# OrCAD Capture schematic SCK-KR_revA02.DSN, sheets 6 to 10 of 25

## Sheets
6 SOM240_1 Connector: size Custom
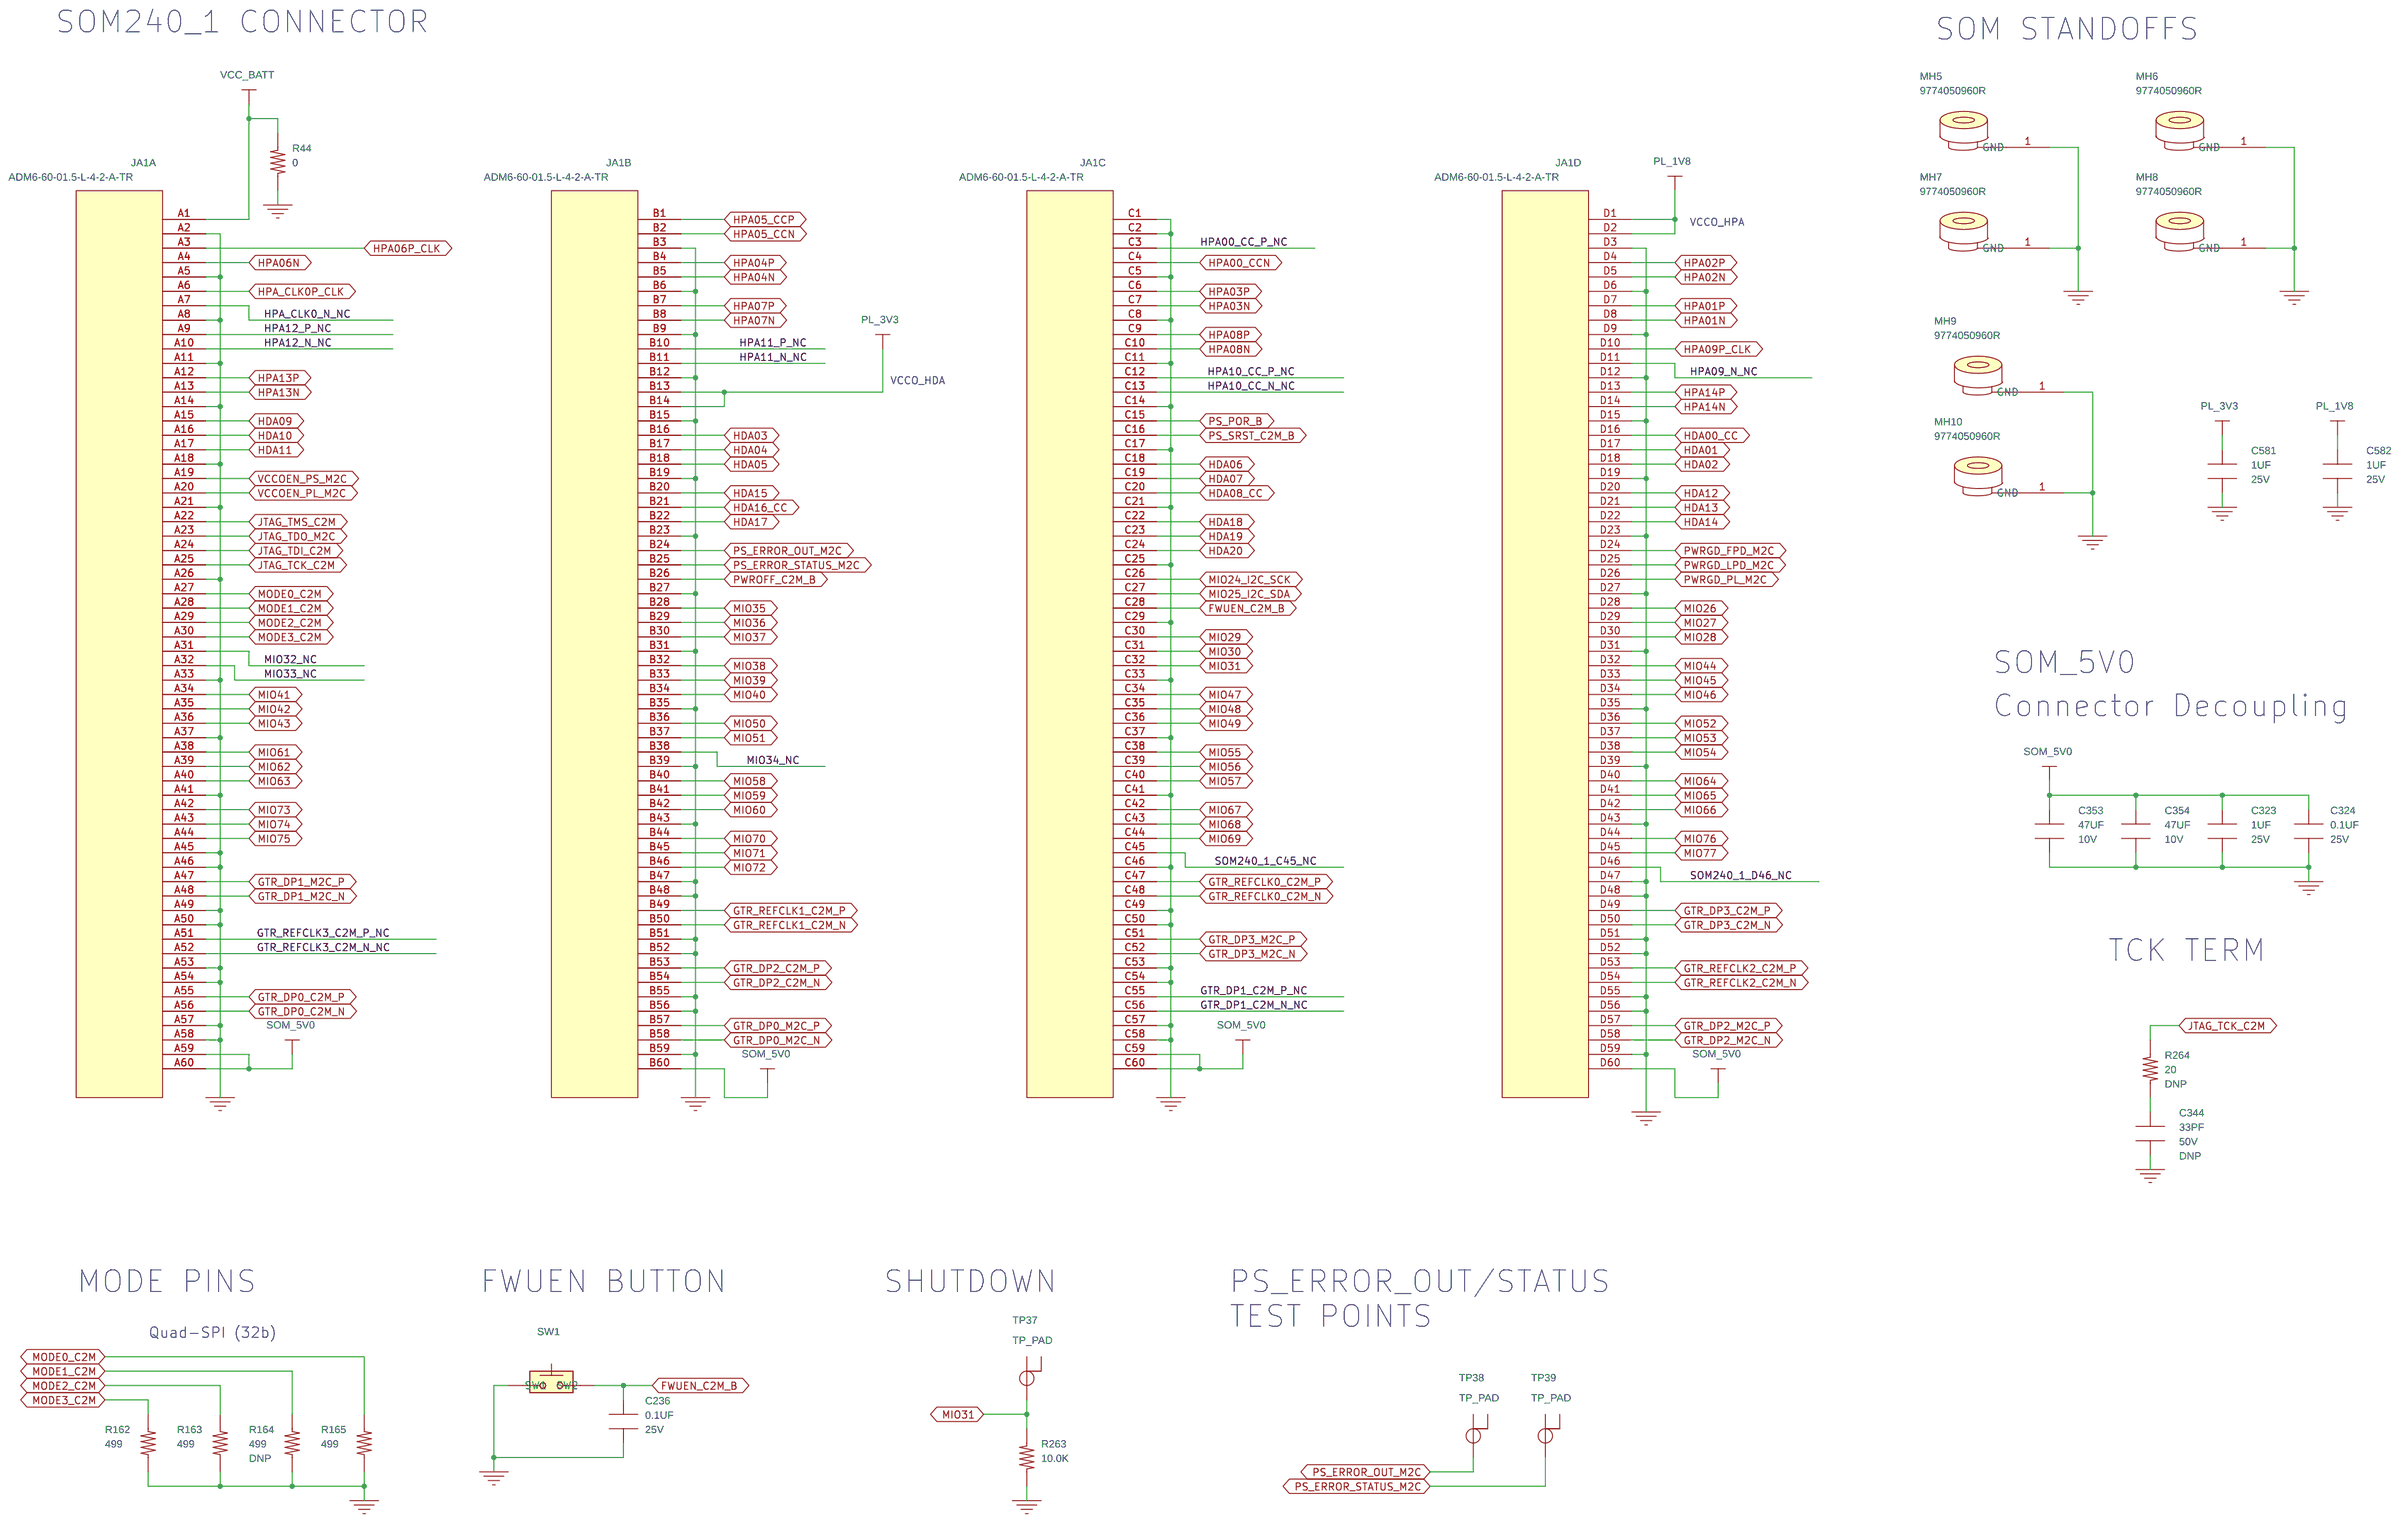
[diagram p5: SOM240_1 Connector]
7 SOM240_2 Connector: size Custom
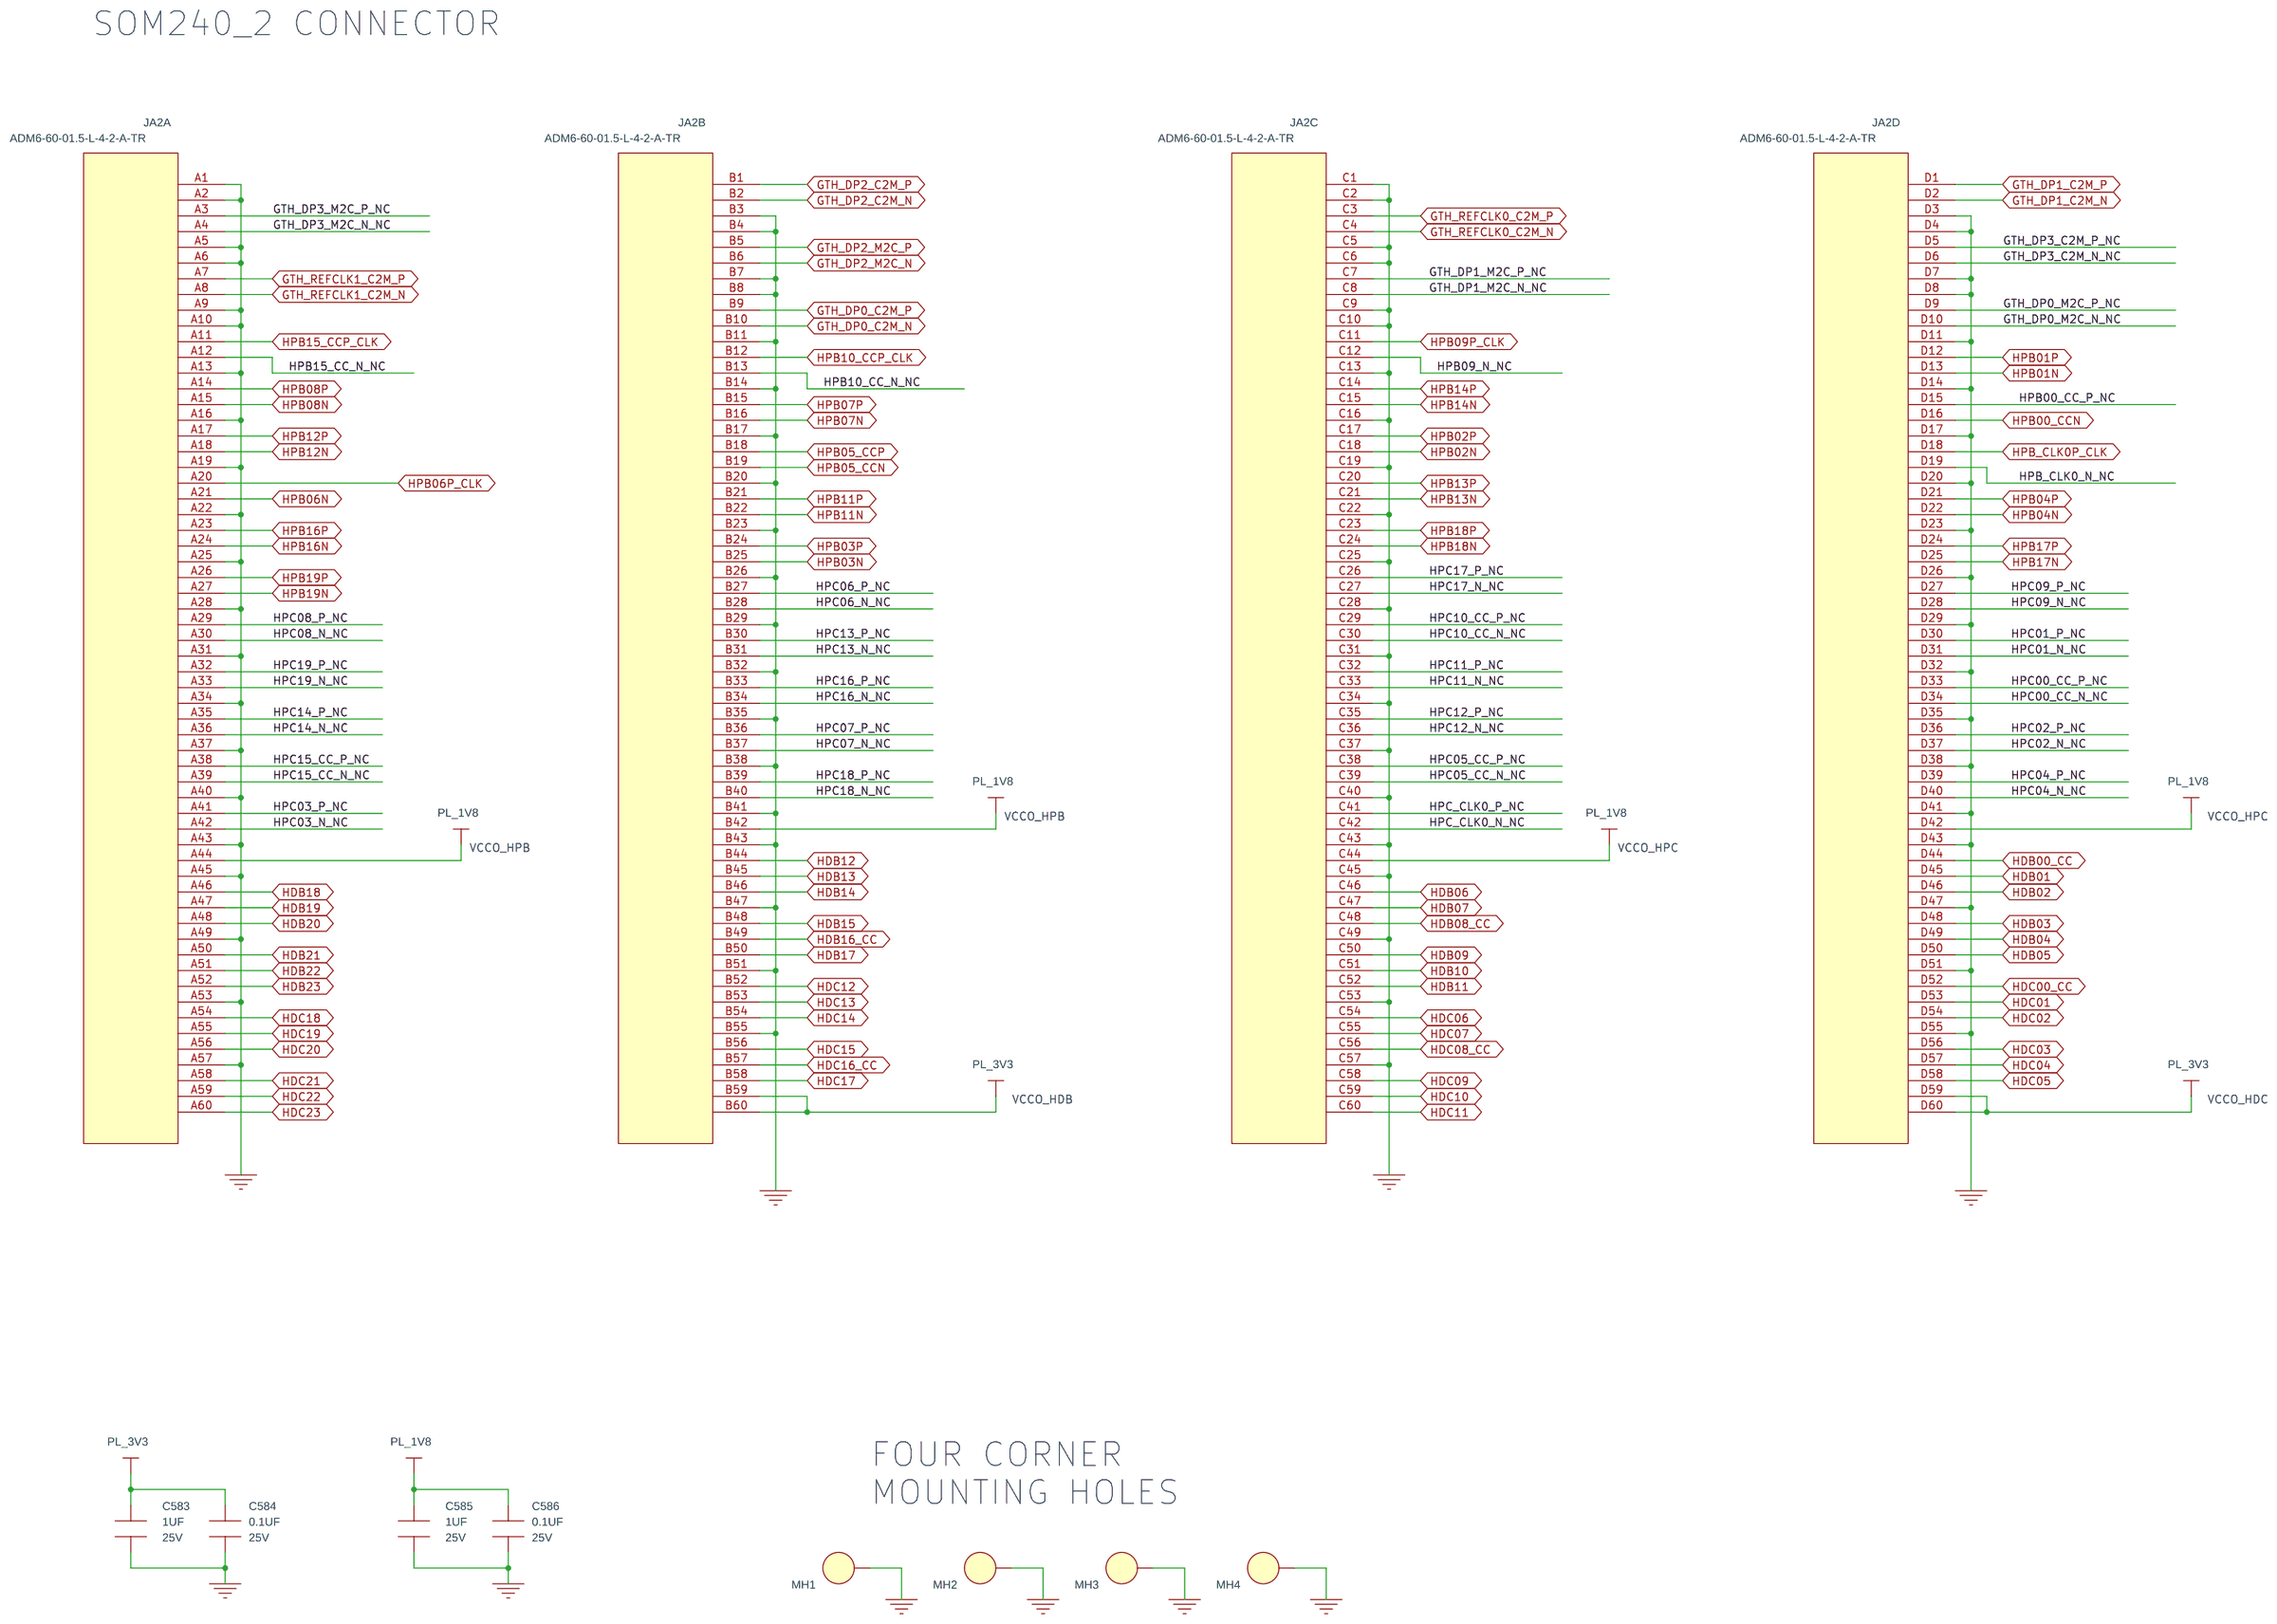
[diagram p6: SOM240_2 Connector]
8 WD, LEDs: size Custom
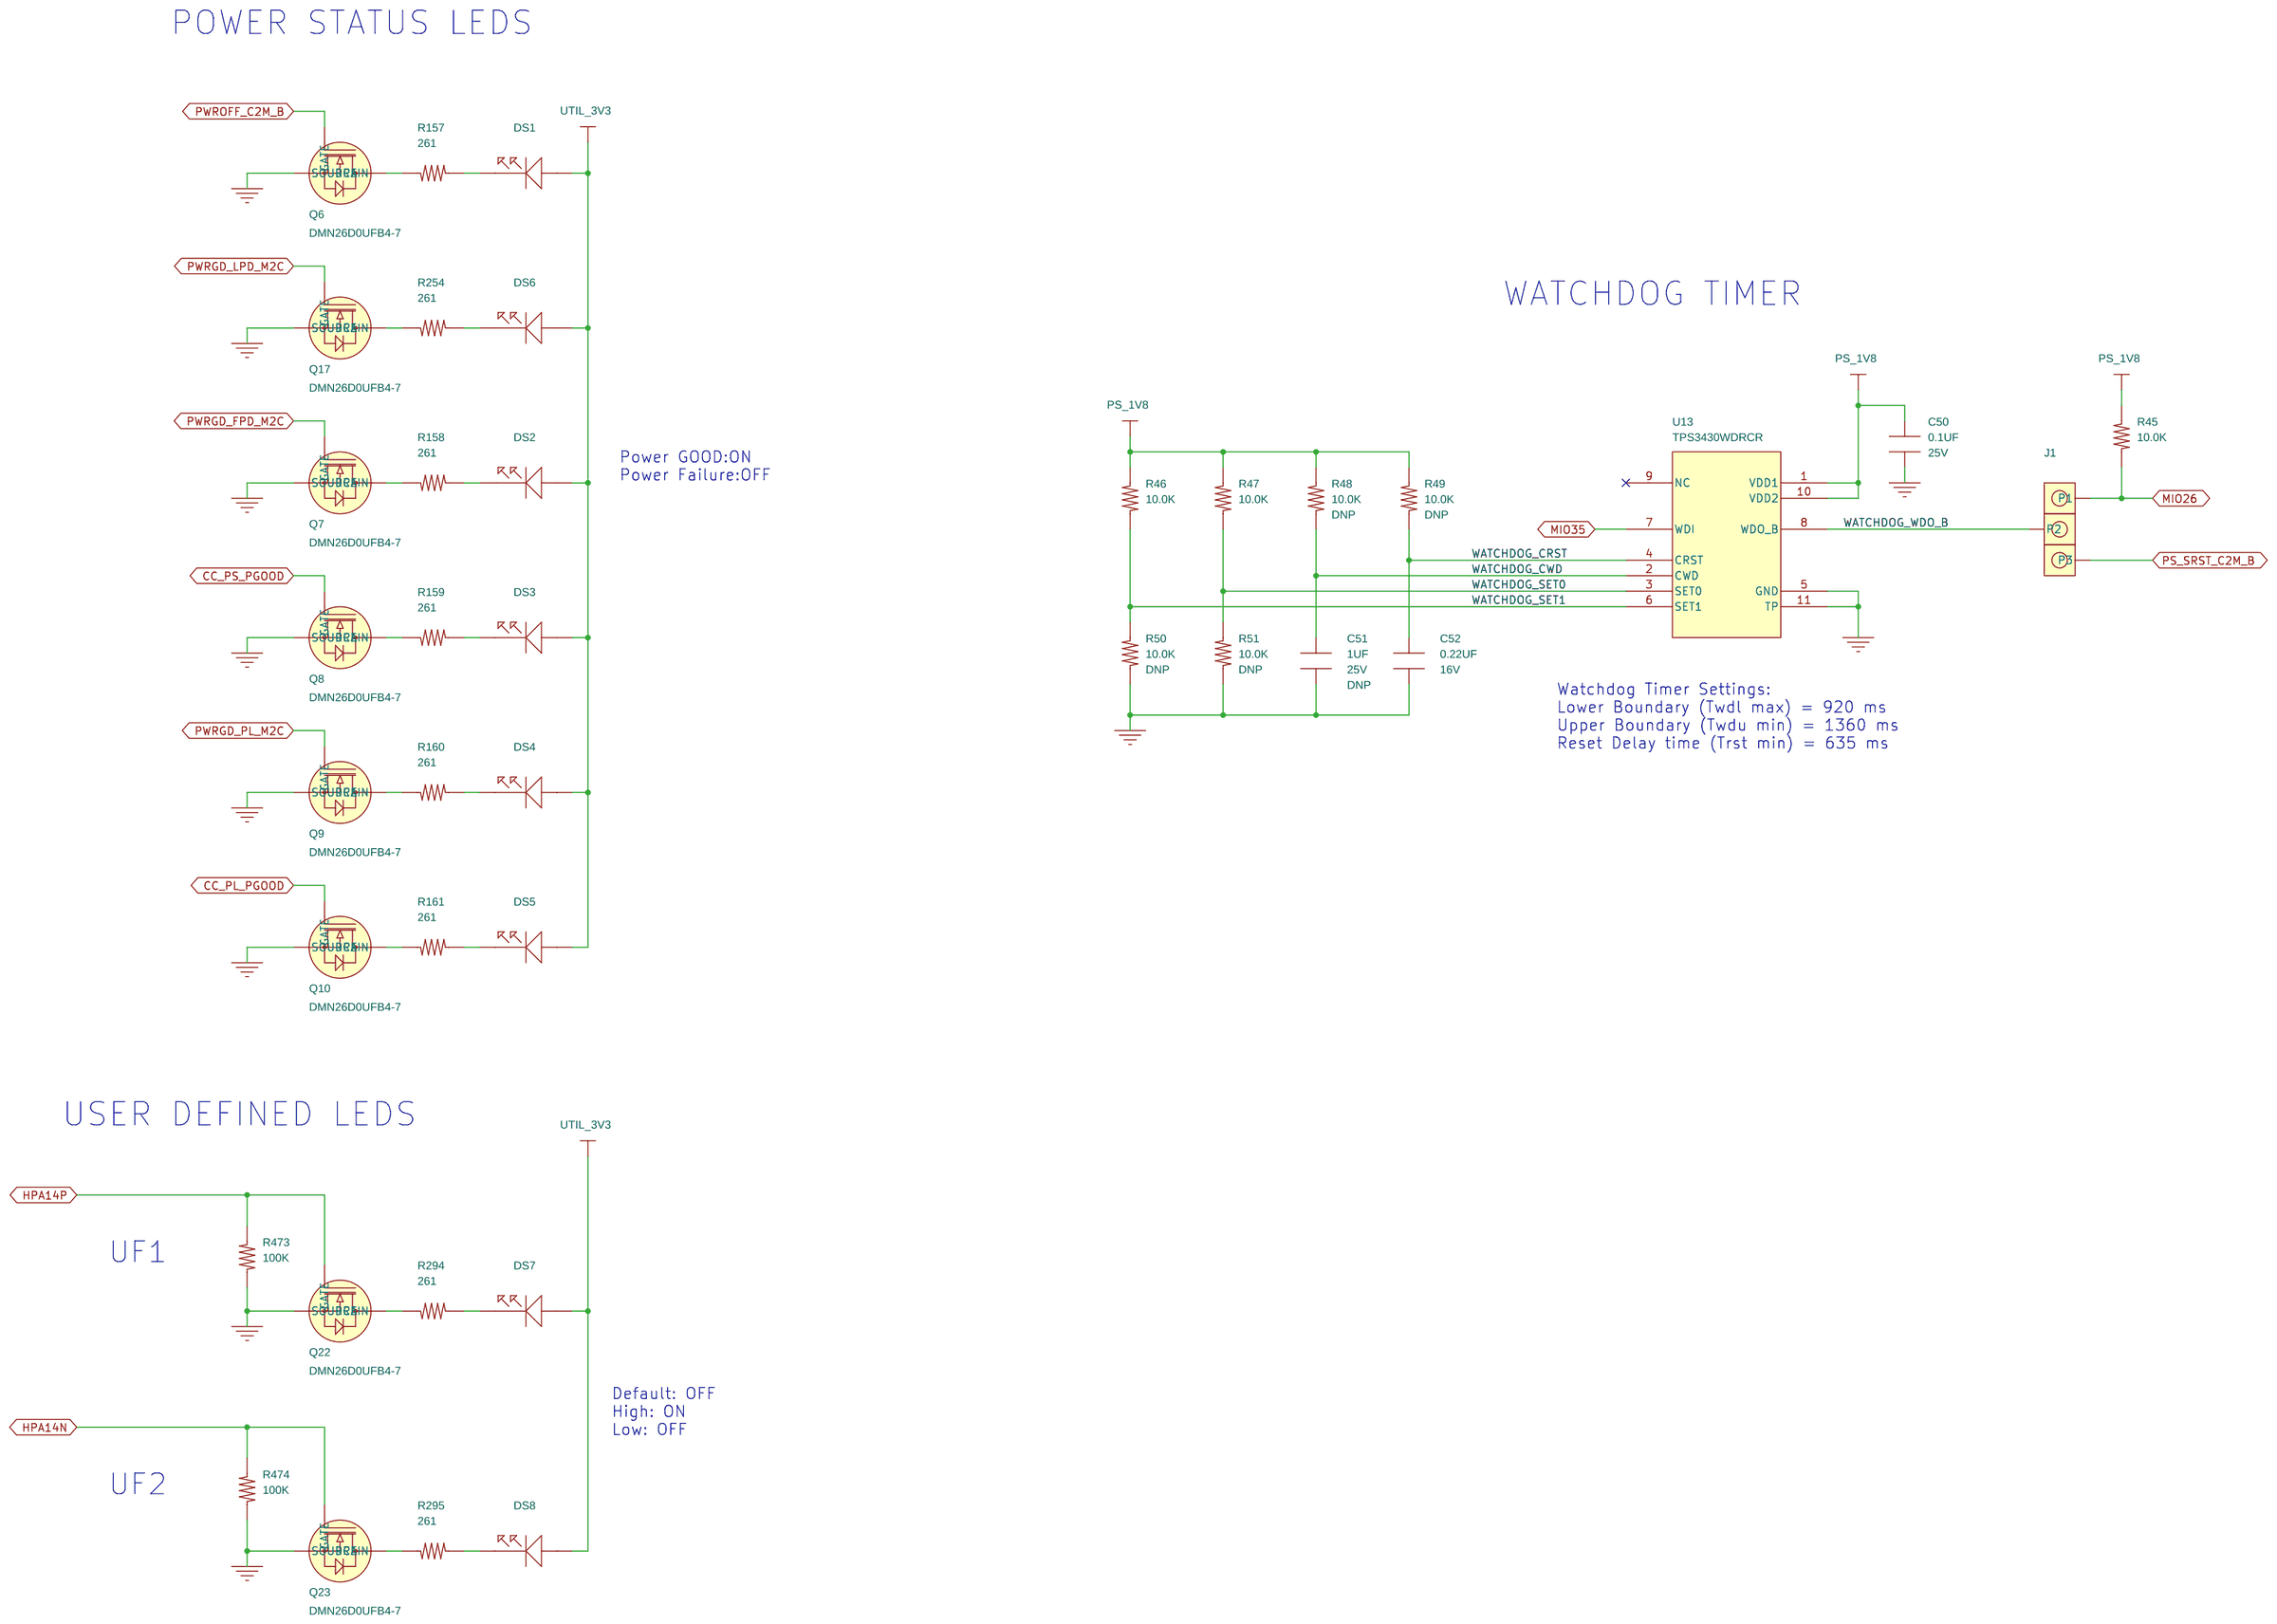
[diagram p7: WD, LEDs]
9 JTAG/UART: size Custom
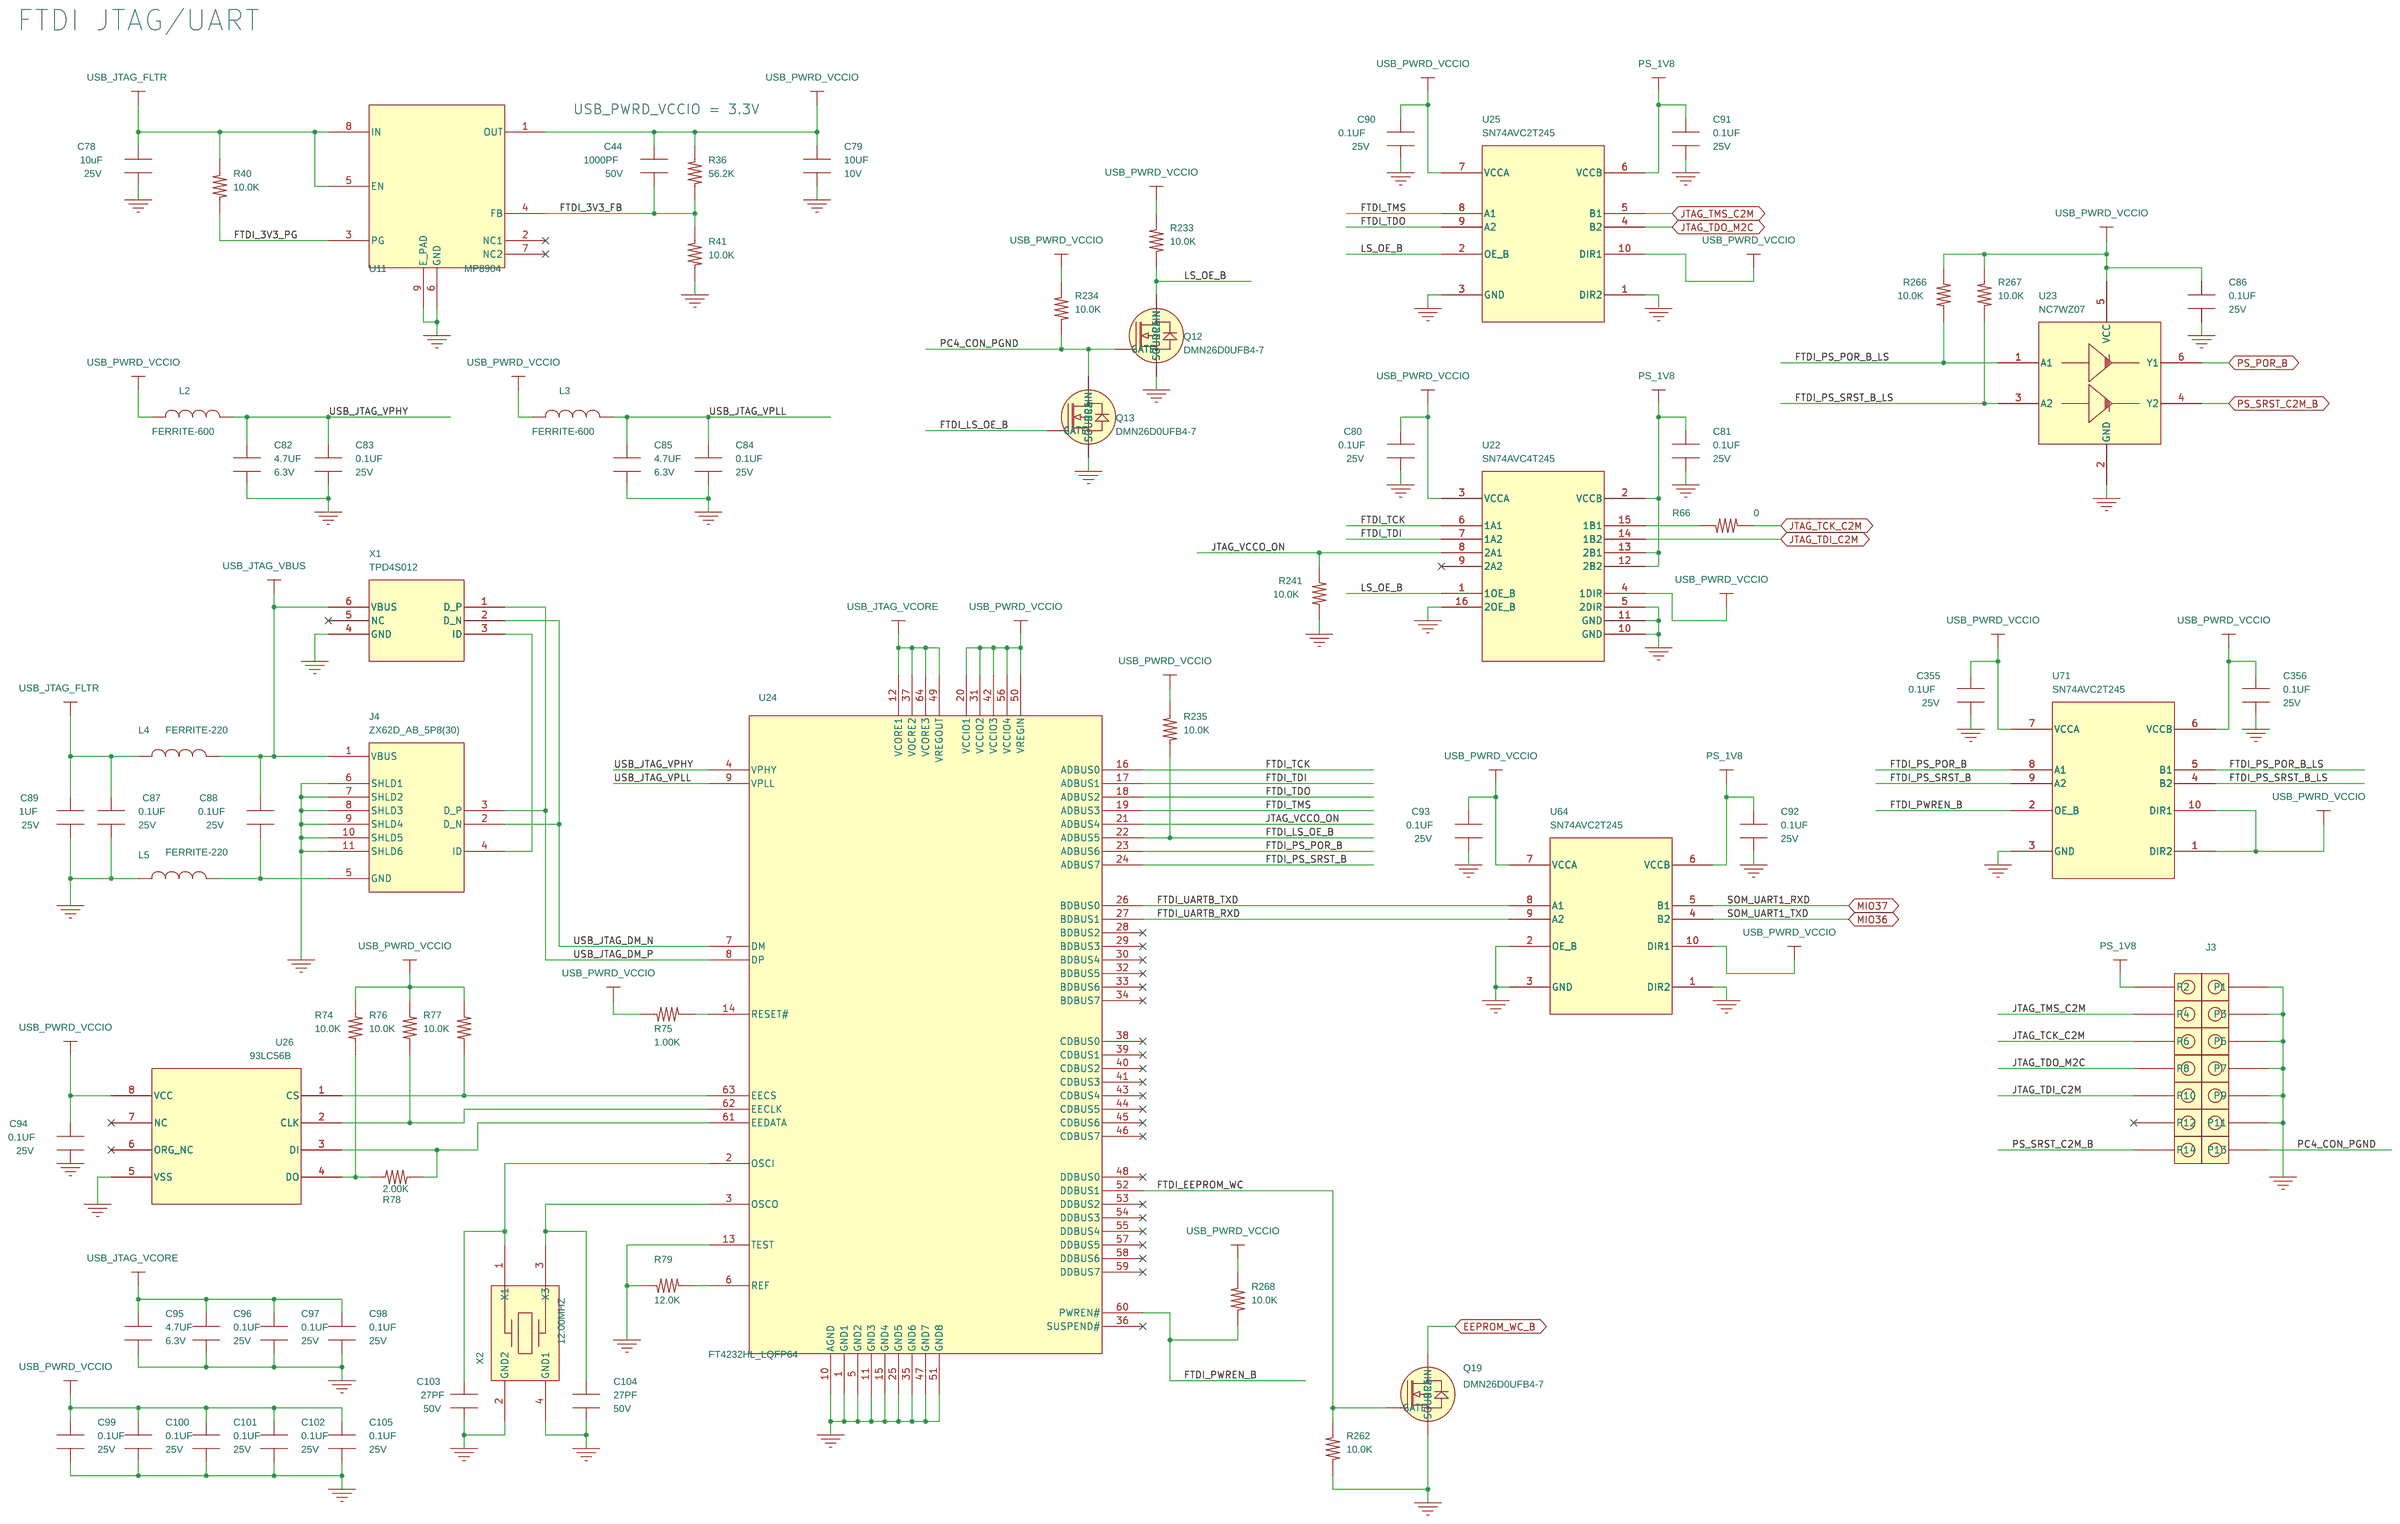
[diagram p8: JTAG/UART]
10 PMOD1&2: size Custom
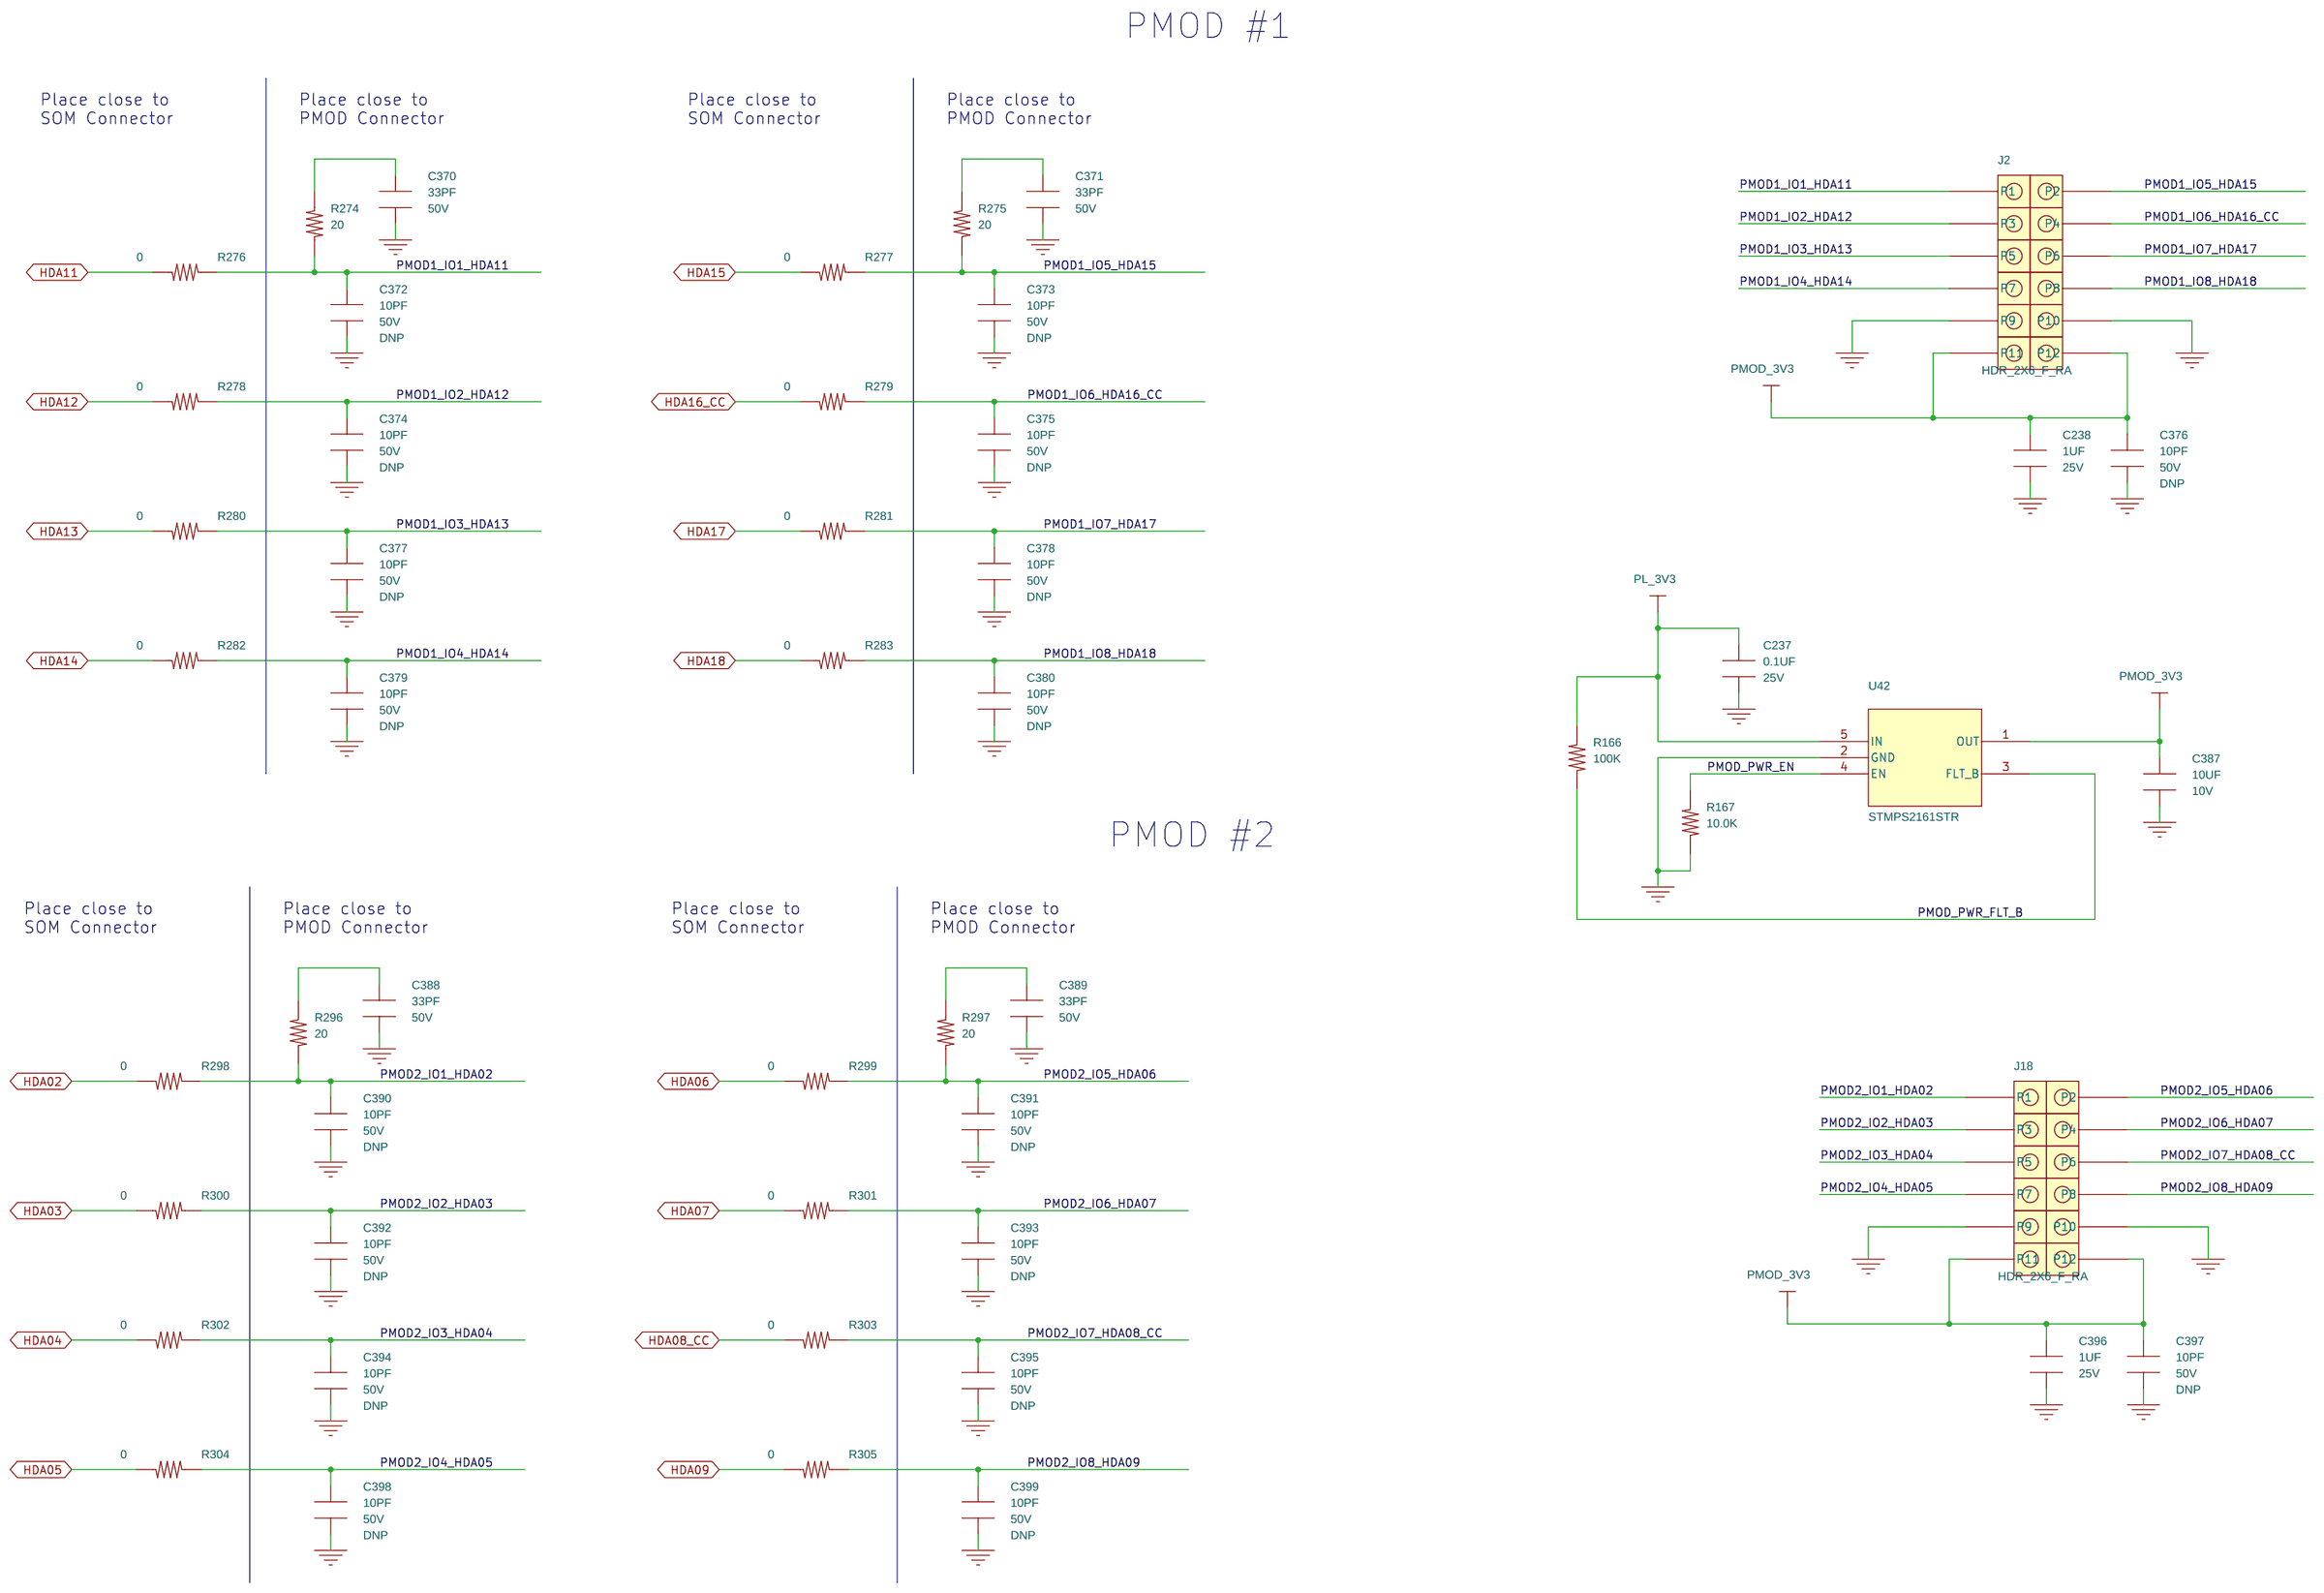
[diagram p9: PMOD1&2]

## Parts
sheet JTAG/UART
C44  1000PF  [CAPC100X50X55]
C78  10uF  [CAPC200X125X145]
C79  10UF  [CAPC100X50X70]
C80  0.1UF  [CAPC100X50X55]
C81  0.1UF  [CAPC100X50X55]
C82  4.7UF  [CAPC100X50X60]
C83  0.1UF  [CAPC100X50X55]
C84  0.1UF  [CAPC100X50X55]
C85  4.7UF  [CAPC100X50X60]
C86  0.1UF  [CAPC100X50X55]
C87  0.1UF  [CAPC100X50X55]
C88  0.1UF  [CAPC100X50X55]
C89  1UF  [CAPC100X50X70]
C90  0.1UF  [CAPC100X50X55]
C91  0.1UF  [CAPC100X50X55]
C92  0.1UF  [CAPC100X50X55]
C93  0.1UF  [CAPC100X50X55]
C94  0.1UF  [CAPC100X50X55]
C95  4.7UF  [CAPC100X50X60]
C96  0.1UF  [CAPC100X50X55]
C97  0.1UF  [CAPC100X50X55]
C98  0.1UF  [CAPC100X50X55]
C99  0.1UF  [CAPC100X50X55]
C100  0.1UF  [CAPC100X50X55]
C101  0.1UF  [CAPC100X50X55]
C102  0.1UF  [CAPC100X50X55]
C103  27PF  [CAPC100X50X55]
C104  27PF  [CAPC100X50X55]
C105  0.1UF  [CAPC100X50X55]
C355  0.1UF  [CAPC100X50X55]
C356  0.1UF  [CAPC100X50X55]
J3  87832-1420  [87832_1420]
J4  ZX62D_AB_5P8(30)  [CON_HR_ZX62D_AB_5P8]
L2  FERRITE-600  [INDC200X125X110]
L3  FERRITE-600  [INDC200X125X110]
L4  FERRITE-220  [INDC160X80X95]
L5  FERRITE-220  [INDC160X80X95]
Q12  DMN26D0UFB4-7  [DFN_105X65x40_3]
Q13  DMN26D0UFB4-7  [DFN_105X65x40_3]
Q19  DMN26D0UFB4-7  [DFN_105X65x40_3]
R36  56.2K  [RESC100X50X40]
R40  10.0K  [RESC100X50X40]
R41  10.0K  [RESC100X50X40]
R66  0  [RESC100X50X40]
R74  10.0K  [RESC100X50X40]
R75  1.00K  [RESC100X50X40]
R76  10.0K  [RESC100X50X40]
R77  10.0K  [RESC100X50X40]
R78  2.00K  [RESC100X50X40]
R79  12.0K  [RESC100X50X40]
R233  10.0K  [RESC100X50X40]
R234  10.0K  [RESC100X50X40]
R235  10.0K  [RESC100X50X40]
R241  10.0K  [RESC100X50X40]
R262  10.0K  [RESC100X50X40]
R266  10.0K  [RESC100X50X40]
R267  10.0K  [RESC100X50X40]
R268  10.0K  [RESC100X50X40]
U11  MP8904  [QFN_MP8904DD_8]
U22  SN74AVC4T245  [QFN_RSV_16]
U23  NC7WZ07  [SC70_6]
U24  FT4232HL_LQFP64  [LQFP_64]
U25  SN74AVC2T245  [QFN40P140X180X55-10]
U26  93LC56B  [SOIC8P127W390]
U64  SN74AVC2T245  [QFN40P140X180X55-10]
U71  SN74AVC2T245  [QFN40P140X180X55-10]
X1  TPD4S012  [DRY_6_SON]
X2  12.00MHZ  [xtal_320x250X71]
sheet PMOD1&2
C237  0.1UF  [CAPC100X50X55]
C238  1UF  [CAPC100X50X70]
C370  33PF  [CAPC100X50X56]
C371  33PF  [CAPC100X50X56]
C372  10PF  [CAPC100X50X55]
C373  10PF  [CAPC100X50X55]
C374  10PF  [CAPC100X50X55]
C375  10PF  [CAPC100X50X55]
C376  10PF  [CAPC100X50X55]
C377  10PF  [CAPC100X50X55]
C378  10PF  [CAPC100X50X55]
C379  10PF  [CAPC100X50X55]
C380  10PF  [CAPC100X50X55]
C387  10UF  [CAPC100X50X70]
C388  33PF  [CAPC100X50X56]
C389  33PF  [CAPC100X50X56]
C390  10PF  [CAPC100X50X55]
C391  10PF  [CAPC100X50X55]
C392  10PF  [CAPC100X50X55]
C393  10PF  [CAPC100X50X55]
C394  10PF  [CAPC100X50X55]
C395  10PF  [CAPC100X50X55]
C396  1UF  [CAPC100X50X70]
C397  10PF  [CAPC100X50X55]
C398  10PF  [CAPC100X50X55]
C399  10PF  [CAPC100X50X55]
J2  HDR_2X6_F_RA  [HDR_F2X6_PMOD]
J18  HDR_2X6_F_RA  [HDR_F2X6_PMOD]
R166  100K  [RESC100X50X40]
R167  10.0K  [RESC100X50X40]
R274  20  [RESC100X50X40]
R275  20  [RESC100X50X40]
R276  0  [RESC100X50X40]
R277  0  [RESC100X50X40]
R278  0  [RESC100X50X40]
R279  0  [RESC100X50X40]
R280  0  [RESC100X50X40]
R281  0  [RESC100X50X40]
R282  0  [RESC100X50X40]
R283  0  [RESC100X50X40]
R296  20  [RESC100X50X40]
R297  20  [RESC100X50X40]
R298  0  [RESC100X50X40]
R299  0  [RESC100X50X40]
R300  0  [RESC100X50X40]
R301  0  [RESC100X50X40]
R302  0  [RESC100X50X40]
R303  0  [RESC100X50X40]
R304  0  [RESC100X50X40]
R305  0  [RESC100X50X40]
U42  STMPS2161STR  [SOT95P280X145_5]
sheet SOM240_1 Connector
C236  0.1UF  [CAPC100X50X55]
C323  1UF  [CAPC100X50X70]
C324  0.1UF  [CAPC100X50X55]
C344  33PF  [CAPC100X50X56]
C353  47UF  [CAPC200X125X125]
C354  47UF  [CAPC200X125X125]
C581  1UF  [CAPC100X50X70]
C582  1UF  [CAPC100X50X70]
JA1  ADM6-60-01.5-L-4-2-A-TR  [CON_SAMTEC_ADM6_60_4]  (sections A,B,C,D)
MH5  9774050960R  [CON_WE_WA-SMST_6MM]
MH6  9774050960R  [CON_WE_WA-SMST_6MM]
MH7  9774050960R  [CON_WE_WA-SMST_6MM]
MH8  9774050960R  [CON_WE_WA-SMST_6MM]
MH9  9774050960R  [CON_WE_WA-SMST_6MM]
MH10  9774050960R  [CON_WE_WA-SMST_6MM]
R44  0  [RESC100X50X40]
R162  499  [RESC100X50X40]
R163  499  [RESC100X50X40]
R164  499  [RESC100X50X40]
R165  499  [RESC100X50X40]
R263  10.0K  [RESC100X50X40]
R264  20  [RESC100X50X40]
SW1  B3U-1000P  [SW_OMRON_2P]
TP37  TP_PAD  [TP_PAD]
TP38  TP_PAD  [TP_PAD]
TP39  TP_PAD  [TP_PAD]
sheet SOM240_2 Connector
C583  1UF  [CAPC100X50X70]
C584  0.1UF  [CAPC100X50X55]
C585  1UF  [CAPC100X50X70]
C586  0.1UF  [CAPC100X50X55]
JA2  ADM6-60-01.5-L-4-2-A-TR  [CON_SAMTEC_ADM6_60_4]  (sections A,B,C,D)
MH1  MH_NP_M3_SO_600  [MH_NP_M3_SO_600]
MH2  MH_NP_M3_SO_600  [MH_NP_M3_SO_600]
MH3  MH_NP_M3_SO_600  [MH_NP_M3_SO_600]
MH4  MH_NP_M3_SO_600  [MH_NP_M3_SO_600]
sheet WD, LEDs
C50  0.1UF  [CAPC100X50X55]
C51  1UF  [CAPC100X50X70]
C52  0.22UF  [CAPC100X50X55]
DS1  LED-GRN-SMT  [LED_0603]
DS2  LED-GRN-SMT  [LED_0603]
DS3  LED-GRN-SMT  [LED_0603]
DS4  LED-GRN-SMT  [LED_0603]
DS5  LED-GRN-SMT  [LED_0603]
DS6  LED-GRN-SMT  [LED_0603]
DS7  LED-GRN-SMT  [LED_0603]
DS8  LED-GRN-SMT  [LED_0603]
J1  HDR_1X3  [HDR_1X3]
Q6  DMN26D0UFB4-7  [DFN_105X65x40_3]
Q7  DMN26D0UFB4-7  [DFN_105X65x40_3]
Q8  DMN26D0UFB4-7  [DFN_105X65x40_3]
Q9  DMN26D0UFB4-7  [DFN_105X65x40_3]
Q10  DMN26D0UFB4-7  [DFN_105X65x40_3]
Q17  DMN26D0UFB4-7  [DFN_105X65x40_3]
Q22  DMN26D0UFB4-7  [DFN_105X65x40_3]
Q23  DMN26D0UFB4-7  [DFN_105X65x40_3]
R45  10.0K  [RESC100X50X40]
R46  10.0K  [RESC100X50X40]
R47  10.0K  [RESC100X50X40]
R48  10.0K  [RESC100X50X40]
R49  10.0K  [RESC100X50X40]
R50  10.0K  [RESC100X50X40]
R51  10.0K  [RESC100X50X40]
R157  261  [RESC100X50X40]
R158  261  [RESC100X50X40]
R159  261  [RESC100X50X40]
R160  261  [RESC100X50X40]
R161  261  [RESC100X50X40]
R254  261  [RESC100X50X40]
R294  261  [RESC100X50X40]
R295  261  [RESC100X50X40]
R473  100K  [RESC100X50X40]
R474  100K  [RESC100X50X40]
U13  TPS3430WDRCR  [VSON-CLIP11_3X3MM]

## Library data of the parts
C44 = CAP_NP: Cap Cer 1nF 10% 50V X7R 0402; ALT_SYMBOLS: CAPC100X50X55RND; Agile Part Number: CAP-00036-01; Barcode: 100013; CIP Link: http://xsjbrdwin1/CIP-E/Component/Index/All?pn=100013; Dielectric Type: X7R; Manufacturer: MURATA; Manufacturer PN: GCM155R71H102KA37D; Part Type: CERAMIC; Tolerance: 10%; Voltage: 50V
C78 = CAP_NP: Cap Cer 10uF 10% 25V X7S 0805; Agile Part Number: CAP-00294-01; CIP Link: http://xsjbrdwin1/CIP-E/Component/Index/All?pn=10000021; Manufacturer: Murata Electronics; Manufacturer PN: GRM21BC71E106KE11L; OWNER: 3670; PRICE: 0.04; Part Type: CERAMIC; PartType: CERAMIC; ROHS: Yes; Tolerance: 10%; Voltage: 25V; barcode: 10000021; Datasheet: https://search.murata.co.jp/Ceramy/image/img/A01X/G101/ENG/GRM21BC71E106KE11-01.pdf
C79 = CAP_NP: Cap Cer 10uF 20% 10V X5R 0402; Agile Part Number: CAP-00170-01; CIP Link: http://xsjbrdwin1/CIP-E/Component/Index/All?pn=100197; Dielectric Type: X5R; Manufacturer: SAMSUNG; Manufacturer PN: CL05A106MP5NUNC; OWNER: 3670; PRICE: 0.04; Part Type: CERAMIC; PartType: CERAMIC; ROHS: Yes; Tolerance: 20%; Voltage: 10V; barcode: 100197
C80 C81 C83 C84 C86-C88 C90-C94 C96-C102 C105 C355 C356 = CAP_NP: Cap Cer 100nF 10% 25V X5R 0402; ALT_SYMBOLS: CAPC100X50X55RND; Agile Part Number: CAP-00068-01; CIP Link: http://xsjbrdwin1/CIP-E/Component/Index/All?pn=100040; Dielectric Type: X5R; Manufacturer: TAIYO YUDEN; Manufacturer PN: TMK105BJ104KV-F; OWNER: 4001; PRICE: 0.01; Part Type: CERAMIC; PartType: CERAMIC; ROHS: Yes; Tolerance: 10%; Voltage: 25V; barcode: 100040
C82 C85 C95 = CAP_NP: Cap Cer 4.7uF 20% 6.3V X5R 0402; ALT_SYMBOLS: CAPC100X50X60RND; Agile Part Number: CAP-00085-01; CIP Link: http://xsjbrdwin1/CIP-E/Component/Index/All?pn=100067; Dielectric Type: X5R; Manufacturer: MURATA; Manufacturer PN: GRM155R60J475ME47D; OWNER: 3709; PRICE: 0.06; Part Type: CERAMIC; PartType: CERAMIC; ROHS: Yes; Tolerance: 20%; Voltage: 6.3V; barcode: 100067
C89 C238 C323 C396 C581-C583 C585 = CAP_NP: Cap Cer 1uF 10% 25V X6S 0402; ALT_SYMBOLS: CAPC100X50X55RND; Agile Part Number: CAP-00009-01; Barcode: 100269; CIP Link: http://xsjbrdwin1/CIP-E/Component/Index/All?pn=100269; Dielectric Type: X6S; Manufacturer: MURATA; Manufacturer PN: GRM155C81E105KE11D; Part Type: CERAMIC; Tolerance: 10%; Voltage: 25V
C103 C104 = CAP_NP: Cap Cer 27pF 5% 50V C0G 0402; ALT_SYMBOLS: CAPC100X50X55RND; Agile Part Number: CAP-00037-01; CIP Link: http://xsjbrdwin1/CIP-E/Component/Index/All?pn=100217; Dielectric Type: NP0; Manufacturer: TDK; Manufacturer PN: CGA2B2C0G1H270J050BA; OWNER: 3670; PRICE: 0.01; Part Type: CERAMIC; PartType: CERAMIC; ROHS: Yes; Tolerance: 5%; Voltage: 50V; barcode: 100217
J3 = HDR_2X7: Conn Hdr Male Vert 14 Pos 2x7 2mm P Black SMT Shrouded with Pegs; Agile Part Number: CON-00111-01; Barcode: 400030; CIP Link: http://xsjbrdwin1/CIP-E/Component/Index/All?pn=400030; Manufacturer: MOLEX; Manufacturer PN: 0878321420; OWNER: 4001; PRICE: 1.34; Part Type: RECEPTACLE; PartType: RECEPTACLE; Pins: 14PINS; Pitch: 2MM; ROHS: Yes
J4 = CONN_USB_MICRO_B_TH: Conn Rcpt Micro USB 2.0 Type AB RA 0.65mm P Gray SMT/TH; Agile Part Number: CON-00008-01; Barcode: 400014; CIP Link: http://xsjbrdwin1/CIP-E/Component/Index/All?pn=400014; Manufacturer: HIROSE; Manufacturer PN: ZX62D-AB-5P8(30); OWNER: 13503; PRICE: 0.43; Part Type: RECEPTACLE; PartType: RECEPTACLE; Pins: 5PIN; ROHS: Yes
L2 L3 = IND: Bead 600R 25% 500mA 300mR 0805; Agile Part Number: FLT-00005-01; Barcode: 300009; CIP Link: http://xsjbrdwin1/CIP-E/Component/Index/All?pn=300009; Manufacturer: LAIRD; Manufacturer PN: HZ0805E601R-10; OWNER: 4001; Part Type: FERRITE; PartType: FERRITE; ROHS: Yes
L4 L5 = IND: Bead 220R 25% 2A 50mR 0603; Agile Part Number: IND-00016-01; Barcode: 300010; CIP Link: http://xsjbrdwin1/CIP-E/Component/Index/All?pn=300010; Manufacturer: TDK Corporation; Manufacturer PN: MPZ1608S221ATA00; OWNER: 4001; PRICE: 0.02; Part Type: FERRITE; PartType: FERRITE; ROHS: Yes
Q6-Q10 Q12 Q13 Q17 Q19 Q22 Q23 = DMN26D0UFB4: MOSFET N-CH 20V 230MA DFN; Agile Part Number: TRN-00054-01; Barcode: 83000008; CIP Link: http://xsjbrdwin1/CIP-E/Component/Index/All?pn=83000008; Manufacturer: Diodes Incorporated; Part Type: FET; Rated Power: 350mW (Ta); Datasheet: https://www.diodes.com/assets/Datasheets/ds31775.pdf
R36 = RES: Res 56K2 1% 1/16W 100PPM 50V 0402; Agile Part Number: RES-00044-01; Barcode: 200256; CIP Link: http://xsjbrdwin1/CIP-E/Component/Index/All?pn=200256; Manufacturer: PANASONIC; Manufacturer PN: ERJ2RKF5622X; Part Type: SMT - 1%; Rated Power: 1/16W; Tolerance: 1%
R40 R41 R45-R47 R167 R233-R235 R241 R262 R263 R266-R268 = RES: Res 10K 1% 1/16W 100PPM 50V 0402; ALT_SYMBOLS: RESC100X50X40RND; Agile Part Number: RES-00030-01; Barcode: 200025; CIP Link: http://xsjbrdwin1/CIP-E/Component/Index/All?pn=200025; Manufacturer: PANASONIC; Manufacturer PN: ERJ2RKF1002X; Part Type: SMT - 1%; Rated Power: 1/16W; Tolerance: 1%
R66 = RES: Res 0R 50mR 1A 0402; ALT_SYMBOLS: RESC100X50X40RND; Agile Part Number: RES-00010-01; Barcode: 200012; CIP Link: http://xsjbrdwin1/CIP-E/Component/Index/All?pn=200012; Manufacturer: PANASONIC; Manufacturer PN: ERJ2GE0R00X; OWNER: 4001; PRICE: 0.01; Part Type: SMT - 5%; PartType: SMT - 5%; Power: 1/10W; ROHS: Yes; Tolerance: 5%; primarykey: 13
R74 R76 R77 = RES: Res 10K 1% 1/16W 100PPM 50V 0402; ALT_SYMBOLS: RESC100X50X40RND; Agile Part Number: RES-00030-01; Barcode: 200025; CIP Link: http://xsjbrdwin1/CIP-E/Component/Index/All?pn=200025; Manufacturer: PANASONIC; Manufacturer PN: ERJ2RKF1002X; OWNER: 4001; PRICE: 0; Part Type: SMT - 1%; PartType: SMT - 1%; Power: 1/10W; ROHS: Yes; Rated Power: 1/16W; Tolerance: 1%; primarykey: 1
R75 = RES: Res 1K 1% 1/16W 100PPM 50V 0402; ALT_SYMBOLS: RESC100X50X40RND; Agile Part Number: RES-00027-01; Barcode: 200098; CIP Link: http://xsjbrdwin1/CIP-E/Component/Index/All?pn=200098; Manufacturer: PANASONIC; Manufacturer PN: ERJ2RKF1001X; OWNER: 4001; PRICE: 0; Part Type: SMT - 1%; PartType: SMT - 1%; Power: 1/16W; ROHS: Yes; Rated Power: 1/16W; Tolerance: 1%; primarykey: 7
R78 = RES: Res 2K 1% 1/16W 100PPM 50V 0402; ALT_SYMBOLS: RESC100X50X40RND; Agile Part Number: RES-00003-01; Barcode: 200096; CIP Link: http://xsjbrdwin1/CIP-E/Component/Index/All?pn=200096; Manufacturer: PANASONIC; Manufacturer PN: ERJ2RKF2001X; OWNER: 4001; PRICE: 0.05; Part Type: SMT - 1%; PartType: SMT - 1%; Power: 1/16W; ROHS: Yes; Rated Power: 1/16W; Tolerance: 1%; primarykey: 2
R79 = RES: Res 12K 1% 1/16W 100PPM 50V 0402; ALT_SYMBOLS: RESC100X50X40RND; Agile Part Number: RES-00349-01; Barcode: 200386; CIP Link: http://xsjbrdwin1/CIP-E/Component/Index/All?pn=200386; Manufacturer: PANASONIC; Manufacturer PN: ERJ2RKF1202X; OWNER: 14716; PRICE: 0; Part Type: SMT - 1%; PartType: SMT - 1%; Power: 1/10W; ROHS: Yes; Rated Power: 1/16W; Tolerance: 1%; primarykey: 190
U11 = MP8904: IC LDO 6.5V 500mA Adj QFN-8; Agile Part Number: ICS-00581-01; Barcode: 96000022; CIP Link: http://xsjbrdwin1/CIP-E/Component/Index/All?pn=96000022; Manufacturer: Monolithic Power Systems Inc.; Manufacturer PN: MP8904DD-LF-Z; Part Type: LDO; Datasheet: https://www.monolithicpower.com/pub/media/document/MP8904_r1.02.pdf
U22 = SN74AVC4T245: IC Lvl Trans 4-Bit Bidir 380Mbps 1.2-3.6V 50mA UQFN-16; Agile Part Number: ICS-00049-01; Barcode: 500013; CIP Link: http://xsjbrdwin1/CIP-E/Component/Index/All?pn=500013; Family: BUS TRANSCEIVER; Manufacturer: TEXAS INSTRUMENTS; Manufacturer PN: SN74AVC4T245RSVR; Part Type: BUS TRANSCEIVER; ROHS: Yes
U23 = NC7WZ07: IC Buffer Dual 5V 50mA 3.9nSec SC70-6 Open Drain; Agile Part Number: ICS-00102-01; Barcode: 500086; CIP Link: http://xsjbrdwin1/CIP-E/Component/Index/All?pn=500086; Family: CMOS LOGIC; Manufacturer: ON Semiconductor; Manufacturer PN: NC7WZ07P6X; Part Type: CMOS LOGIC; ROHS: Yes
U24 = FT4232HL: IC PHY USB 2.0 HS Single 480Mbps 3.3V 4-UART/MPSSE LQFP-64; Agile Part Number: ICS-00337-01; Barcode: 500498; CIP Link: http://xsjbrdwin1/CIP-E/Component/Index/All?pn=500498; Family: USB TO UART, JTAG; Manufacturer: FTDI; Manufacturer PN: FT4232HL-REEL; Part Type: USB TO UART, JTAG; ROHS: YES
U25 U64 U71 = SN74AVC2T245: IC Lvl Trans 2-Bit Bidir 500Mbps 1.2-3.6V 50mA UQFN-10; Agile Part Number: ICS-00048-01; Barcode: 500012; CIP Link: http://xsjbrdwin1/CIP-E/Component/Index/All?pn=500012; Manufacturer: TEXAS INSTRUMENTS; Manufacturer PN: SN74AVC2T245RSWR; Part Type: BUS TRANSCEIVER
U26 = 93LC56B: IC EEPROM 2Kb 128x16-Bit Serial 2MHz 2.5V SOIC-8; Agile Part Number: ICS-00335-01; Barcode: 500495; CIP Link: http://xsjbrdwin1/CIP-E/Component/Index/All?pn=500495; Family: MEMORY; Manufacturer: MICROCHIP; Manufacturer PN: 93LC56B-I/SN; Part Type: MEMORY; ROHS: YES
X1 = TPD4S012: TVSD 4-Ch 5.5V 3A 60W SON-6 10KV Contact Discharge; Agile Part Number: ICS-00003-01; Barcode: 500251; CIP Link: http://xsjbrdwin1/CIP-E/Component/Index/All?pn=500251; Family: ESD PROTECTOR; Manufacturer: TEXAS INSTRUMENTS; Manufacturer PN: TPD4S012DRYR; OWNER: 3501; PRICE: 0; Part Type: ESD PROTECTOR; PartType: ZENER; Power: 60MW; ROHS: Yes
X2 = ABM8_XTAL: Xtal 12MHz 200uW 100R 18pF 52PPM 3225; Agile Part Number: XTL-00043-01; Barcode: 60000019; CIP Link: http://xsjbrdwin1/CIP-E/Component/Index/All?pn=60000019; Frequency Stability: 30 ppm; Frequency Tolerance: 20 ppm; Load Capacitance: 18pF; Manufacturer: RALTRON; Manufacturer PN: RH100-12.000-18-2030-EXT-TR; Part Type: CRYSTAL
C50 C236 C237 C324 C584 C586 = CAP_NP: Cap Cer 100nF 10% 25V X5R 0402; ALT_SYMBOLS: CAPC100X50X55RND; Agile Part Number: CAP-00068-01; CIP Link: http://xsjbrdwin1/CIP-E/Component/Index/All?pn=100040; DEVICE: 0_1UF_0402_X7R_50V; Dielectric: X7R; Dielectric Type: X5R; MANF: TAIYO YUDEN; MANF_P/N: UMK105B7104KV-FR; Manufacturer: TAIYO YUDEN; Manufacturer PN: TMK105BJ104KV-F; OWNER: 6176; PRICE: 0.02; Part Type: CERAMIC; PartType: CERAMIC; ROHS: Yes; Tolerance: 10%; Voltage: 25V; barcode: 100040
C370 C371 C388 C389 = CAP_NP: Cap Cer 33pF 5% 50V C0G 0402; ALT_SYMBOLS: CAPC100X50X56RND; Agile Part Number: CAP-00013-01; Barcode: 100188; CIP Link: http://xsjbrdwin1/CIP-E/Component/Index/All?pn=100188; Dielectric Type: NP0; Manufacturer: AVX; Manufacturer PN: 04025A330JAT2A; Part Type: CERAMIC; Tolerance: 5%; Voltage: 50V
C372-C380 C390-C395 C397-C399 = CAP_NP: Cap Cer 10pF 5% 50V C0G 0402; ALT_SYMBOLS: (0402,C402-25,CAPC100X50X55L25NRND,CAPC100X50X55L30NRND,CAPC100X50X55L30N); ASSEMBLY_OPTIONS: DNP; Agile Part Number: CAP-00115-01; Barcode: 100127; CIP Link: http://xsjbrdwin1/CIP-E/Component/Index/All?pn=100127; Dielectric Type: C0G, NP0; Manufacturer: MURATA; Manufacturer PN: GCM1555C1H100JA16D; Part Type: CERAMIC; Tolerance: 5%; Voltage: 50V
C387 = CAP_NP: Cap Cer 10uF 20% 10V X5R 0402; Agile Part Number: CAP-00170-01; Barcode: 100197; CIP Link: http://xsjbrdwin1/CIP-E/Component/Index/All?pn=100197; Dielectric Type: X5R; Manufacturer: SAMSUNG; Manufacturer PN: CL05A106MP5NUNC; Part Type: CERAMIC; Tolerance: 20%; Voltage: 10V
J2 J18 = HDR_2X6: Conn Hdr Female RA 12 Pos 2x6 2.54mm P TH; Agile Part Number: CON-00015-01; Barcode: 390021; CIP Link: http://xsjbrdwin1/CIP-E/Component/Index/All?pn=390021; Manufacturer: SULLINS; Manufacturer PN: PPPC062LJBN-RC; OWNER: 3709; PRICE: 1.58; Part Type: HEADER; PartType: HEADER; Pins: 12PINS; Pitch: 0.100; ROHS: Yes
R166 = RES: Res 100K 1% 1/16W 100PPM 50V 0402; ALT_SYMBOLS: RESC100X50X40RND; Agile Part Number: RES-00011-01; Barcode: 200026; CIP Link: http://xsjbrdwin1/CIP-E/Component/Index/All?pn=200026; Manufacturer: PANASONIC; Manufacturer PN: ERJ2RKF1003X; Part Type: SMT - 1%; Rated Power: 1/16W; Tolerance: 1%
R274 R275 R296 R297 = RES: Res 20R 1% 1/16W 100PPM 50V 0402; ALT_SYMBOLS: RESC100X50X40RND; Agile Part Number: RES-00033-01; Barcode: 200119; CIP Link: http://xsjbrdwin1/CIP-E/Component/Index/All?pn=200119; Manufacturer: VISHAY DALE; Manufacturer PN: CRCW040220R0FKED; Part Type: SMT - 1%; Rated Power: 1/16W; Tolerance: 1%
R44 R276-R283 R298-R305 = RES: Res 0R 50mR 1A 0402; ALT_SYMBOLS: RESC100X50X40RND; Agile Part Number: RES-00010-01; Barcode: 200012; CIP Link: http://xsjbrdwin1/CIP-E/Component/Index/All?pn=200012; Manufacturer: PANASONIC; Manufacturer PN: ERJ2GE0R00X; Part Type: SMT - 5%; Tolerance: 5%
U42 = TPS2065CDBVT: IC Switch Power 1A 2.7-5.5V 125mR SOT23-5 Active Low; Agile Part Number: ICS-00871-01; Barcode: 50000321; CIP Link: http://xsjbrdwin1/CIP-E/Component/Index/All?pn=50000321; Part Type: LOAD SWITCH; Supply Voltage: Not Required
C344 = CAP_NP: Cap Cer 33pF 5% 50V C0G 0402; ALT_SYMBOLS: CAPC100X50X56RND; ASSEMBLY_OPTIONS: DNP; Agile Part Number: CAP-00013-01; Barcode: 100188; CIP Link: http://xsjbrdwin1/CIP-E/Component/Index/All?pn=100188; Dielectric Type: NP0; Manufacturer: AVX; Manufacturer PN: 04025A330JAT2A; Part Type: CERAMIC; Tolerance: 5%; Voltage: 50V
C353 C354 = CAP_NP: CAP CER 47UF 10V X5R 0805; ALT_SYMBOLS: CAPC200X125X125RND; Agile Part Number: CAP-00254-01; Barcode: 100335; CIP Link: http://xsjbrdwin1/CIP-E/Component/Index/All?pn=100335; Dielectric Type: X5R; Manufacturer: MURATA; Manufacturer PN: GRM21BR61A476ME15L; Part Type: CERAMIC; Tolerance: 20%; Voltage: 10V
JA1 JA2 = SAMTEC-ADx6-60X4: Conn Rcpt Male Vert 240 Pos 4x60 0.635mm P Black SMT; Agile Part Number: CON-00383-01; Barcode: 40000092; CIP Link: http://xsjbrdwin1/CIP-E/Component/Index/All?pn=40000092; Manufacturer: Samtec Inc.; Number of Pins: 240; Part Type: CONNECTOR; Pitch: 0.025" (0.64mm); Datasheet: http://suddendocs.samtec.com/catalog_english/adf6.pdf
MH5-MH10 = MECH_SPACER: Standoff Female 3.3mm ID 5mm L 7.4mm OD SMT/TH Steel; Agile Part Number: MEC-00173-01; Barcode: 90000024; CIP Link: http://xsjbrdwin1/CIP-E/Component/Index/All?pn=90000024; Manufacturer: Würth Elektronik; Part Type: Mechanical Part; Datasheet: https://media.digikey.com/pdf/Data%20Sheets/Wurth%20Electronics%20PDFs/WA-SMSx_Performance_Flyer.pdf
R162 R163 R165 = RES: Res 499R 1% 1/16W 100PPM 50V 0402; ALT_SYMBOLS: RESC100X50X40RND; Agile Part Number: RES-00028-01; Barcode: 200071; CIP Link: http://xsjbrdwin1/CIP-E/Component/Index/All?pn=200071; Manufacturer: PANASONIC; Manufacturer PN: ERJ2RKF4990X; Part Type: SMT - 1%; Rated Power: 1/16W; Tolerance: 1%
R164 = RES: Res 499R 1% 1/16W 100PPM 50V 0402; ALT_SYMBOLS: RESC100X50X40RND; ASSEMBLY_OPTIONS: DNP; Agile Part Number: RES-00028-01; Barcode: 200071; CIP Link: http://xsjbrdwin1/CIP-E/Component/Index/All?pn=200071; Manufacturer: PANASONIC; Manufacturer PN: ERJ2RKF4990X; Part Type: SMT - 1%; Rated Power: 1/16W; Tolerance: 1%
R264 = RES: Res 20R 1% 1/16W 100PPM 50V 0402; ALT_SYMBOLS: RESC100X50X40RND; ASSEMBLY_OPTIONS: DNP; Agile Part Number: RES-00033-01; Barcode: 200119; CIP Link: http://xsjbrdwin1/CIP-E/Component/Index/All?pn=200119; Manufacturer: VISHAY DALE; Manufacturer PN: CRCW040220R0FKED; Part Type: SMT - 1%; Rated Power: 1/16W; Tolerance: 1%
SW1 = BTN_MOMENT: Switch SPST-NO Mom 50mA 12V 1.6mm H 1.5Nw SMT IP40; Agile Part Number: SWH-00003-01; Barcode: 440024; CIP Link: http://xsjbrdwin1/CIP-E/Component/Index/All?pn=440024; Manufacturer: OMRON; Part Type: MOMENT
TP37-TP39 = TP: TEST POINT 24mil SM pad; ASSEMBLY_OPTIONS: DNP; Barcode: 96000010; CIP Link: http://xsjbrdwin1/CIP-E/Component/Index/All?pn=96000010; MANF: DNP; MANF_P/N: DNP; OWNER: 3709; Part Type: Unassigned Part Type; PartType: TEST POINT; Pins: 1PIN; ROHS: Yes; Datasheet: NA
MH1-MH4 = HOLE: MOUNTING HOLE, NON-PLATED 3.4MM HOLE; ASSEMBLY_OPTIONS: DNP; Barcode: 96000044; CIP Link: http://xsjbrdwin1/CIP-E/Component/Index/All?pn=96000044
C51 = CAP_NP: Cap Cer 1uF 10% 25V X6S 0402; ALT_SYMBOLS: CAPC100X50X55RND; ASSEMBLY_OPTIONS: DNP; Agile Part Number: CAP-00009-01; Barcode: 100269; CIP Link: http://xsjbrdwin1/CIP-E/Component/Index/All?pn=100269; Dielectric Type: X6S; Manufacturer: MURATA; Manufacturer PN: GRM155C81E105KE11D; Part Type: CERAMIC; Tolerance: 10%; Voltage: 25V
C52 = CAP_NP: Cap Cer 220nF 10% 16V X5R 0402; ALT_SYMBOLS: CAPC100X50X55RND; Agile Part Number: CAP-00048-01; Barcode: 100008; CIP Link: http://xsjbrdwin1/CIP-E/Component/Index/All?pn=100008; Dielectric Type: X5R; Manufacturer: SAMSUNG; Manufacturer PN: CL05A224KO5NNNC; Part Type: CERAMIC; Tolerance: 10%; Voltage: 16V
DS1-DS8 = LED: LED Green Diffused 20mA 5V 570nm 0603; Agile Part Number: DIO-00003-01; Barcode: 300021; CIP Link: http://xsjbrdwin1/CIP-E/Component/Index/All?pn=300021; Manufacturer: LUMEX; Manufacturer PN: SML-LX0603GW-TR; Rated Power: 2.2-20MA; Voltage: 2.2V
J1 = HDR_1X3: Conn Hdr Male Vert 3 Pos 1x3 2.54mm P Black TH Unshrouded; Agile Part Number: CON-00339-01; Barcode: 40000055; CIP Link: http://xsjbrdwin1/CIP-E/Component/Index/All?pn=40000055; Manufacturer: MOLEX; Manufacturer PN: 0022284033; Number of Pins: 3; Part Type: HEADER; Pitch: 0.100" (2.54mm)
R48-R51 = RES: Res 10K 1% 1/16W 100PPM 50V 0402; ALT_SYMBOLS: RESC100X50X40RND; ASSEMBLY_OPTIONS: DNP; Agile Part Number: RES-00030-01; Barcode: 200025; CIP Link: http://xsjbrdwin1/CIP-E/Component/Index/All?pn=200025; Manufacturer: PANASONIC; Manufacturer PN: ERJ2RKF1002X; Part Type: SMT - 1%; Rated Power: 1/16W; Tolerance: 1%
R157-R161 R254 R294 R295 = RES: Res 261R 1% 1/16W 100PPM 50V 0402; ALT_SYMBOLS: RESC100X50X40RND; Agile Part Number: RES-00086-01; Barcode: 200050; CIP Link: http://xsjbrdwin1/CIP-E/Component/Index/All?pn=200050; Manufacturer: PANASONIC; Manufacturer PN: ERJ2RKF2610X; Part Type: SMT - 1%; Rated Power: 1/16W; Tolerance: 1%
R473 R474 = RES: Res 100K 5% 1/16W 200PPM 50V 0402; Agile Part Number: RES-00137-01; Barcode: 200127; CIP Link: http://xsjbrdwin1/CIP-E/Component/Index/All?pn=200127; Manufacturer: PANASONIC; Manufacturer PN: ERJ2GEJ104X; Part Type: SMT - 5%; Rated Power: 1/16W; Tolerance: 5%
U13 = TPS3430: IC OSC WATCHDOG 10VSON; Agile Part Number: ICS-00668-01; Barcode: 50000175; CIP Link: http://xsjbrdwin1/CIP-E/Component/Index/All?pn=50000175; Manufacturer: Texas Instruments; Part Type: IC; Supply Voltage: 1.6V ~ 6.5V; Datasheet: http://www.ti.com/general/docs/suppproductinfo.tsp?distId=10&gotoUrl=http%3A%2F%2Fwww.ti.com%2Flit%2Fgpn%2Ftps3430

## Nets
GND: C50.2 C51.2 C52.2 C78.2 C79.2 C80.2 C81.2 C82.2 C83.2 C84.2 C85.2 C86.2 C87.2 C89.2 C90.2 C91.2 C92.2 C93.2 C94.2 C95.2 C96.2 C97.2 C98.2 C99.2 C100.2 C101.2 C102.2 C103.2 C104.2 C105.2 C236.2 C237.2 C238.2 C323.2 C324.2 C344.2 C353.2 C354.2 C355.2 C356.2 C370.2 C371.2 C372.2 C373.2 C374.2 C375.2 C376.2 C377.2 C378.2 C379.2 C380.2 C387.2 C388.2 C389.2 C390.2 C391.2 C392.2 C393.2 C394.2 C395.2 C396.2 C397.2 C398.2 C399.2 C581.2 C582.2 C583.2 C584.2 C585.2 C586.2 J2.9(P9) J2.10(P10) J3.1(P1) J3.3(P3) J3.5(P5) J3.7(P7) J3.9(P9) J3.11(P11) J4.6(SHLD1) J4.7(SHLD2) J4.8(SHLD3) J4.9(SHLD4) J4.10(SHLD5) J4.11(SHLD6) J18.9(P9) J18.10(P10) JA1.A2 JA1.A5 JA1.A8 JA1.A11 JA1.A14 JA1.A18 JA1.A21 JA1.A26 JA1.A33 JA1.A37 JA1.A41 JA1.A45 JA1.A46 JA1.A49 JA1.A50 JA1.A53 JA1.A54 JA1.A57 JA1.A58 JA1.B3 JA1.B6 JA1.B9 JA1.B12 JA1.B15 JA1.B19 JA1.B23 JA1.B27 JA1.B31 JA1.B35 JA1.B39 JA1.B43 JA1.B47 JA1.B48 JA1.B51 JA1.B52 JA1.B55 JA1.B56 JA1.B59 JA1.C1 JA1.C2 JA1.C5 JA1.C8 JA1.C11 JA1.C14 JA1.C17 JA1.C21 JA1.C25 JA1.C29 JA1.C33 JA1.C37 JA1.C41 JA1.C46 JA1.C49 JA1.C50 JA1.C53 JA1.C54 JA1.C57 JA1.C58 JA1.D3 JA1.D6 JA1.D9 JA1.D12 JA1.D15 JA1.D19 JA1.D23 JA1.D27 JA1.D31 JA1.D35 JA1.D39 JA1.D43 JA1.D47 JA1.D48 JA1.D51 JA1.D52 JA1.D55 JA1.D56 JA1.D59 JA2.A1 JA2.A2 JA2.A5 JA2.A6 JA2.A9 JA2.A10 JA2.A13 JA2.A16 JA2.A19 JA2.A22 JA2.A25 JA2.A28 JA2.A31 JA2.A34 JA2.A37 JA2.A40 JA2.A43 JA2.A45 JA2.A49 JA2.A53 JA2.A57 JA2.B3 JA2.B4 JA2.B7 JA2.B8 JA2.B11 JA2.B14 JA2.B17 JA2.B20 JA2.B23 JA2.B26 JA2.B29 JA2.B32 JA2.B35 JA2.B38 JA2.B41 JA2.B43 JA2.B47 JA2.B51 JA2.B55 JA2.C1 JA2.C2 JA2.C5 JA2.C6 JA2.C9 JA2.C10 JA2.C13 JA2.C16 JA2.C19 JA2.C22 JA2.C25 JA2.C28 JA2.C31 JA2.C34 JA2.C37 JA2.C40 JA2.C43 JA2.C45 JA2.C49 JA2.C53 JA2.C57 JA2.D3 JA2.D4 JA2.D7 JA2.D8 JA2.D11 JA2.D14 JA2.D17 JA2.D20 JA2.D23 JA2.D26 JA2.D29 JA2.D32 JA2.D35 JA2.D38 JA2.D41 JA2.D43 JA2.D47 JA2.D51 JA2.D55 L5.1 MH1.1 MH2.1 MH3.1 MH4.1 MH5.1(GND) MH6.1(GND) MH7.1(GND) MH8.1(GND) MH9.1(GND) MH10.1(GND) Q6.2(SOURCE) Q7.2(SOURCE) Q8.2(SOURCE) Q9.2(SOURCE) Q10.2(SOURCE) Q12.2(SOURCE) Q13.2(SOURCE) Q17.2(SOURCE) Q19.2(SOURCE) Q22.2(SOURCE) Q23.2(SOURCE) R41.2 R44.2 R50.2 R51.2 R79.1 R162.2 R163.2 R164.2 R165.2 R167.2 R241.2 R262.2 R263.2 R473.2 R474.2 SW1.1(SW1) U11.6(GND) U11.9(E_PAD) U13.5(GND) U13.11(TP) U22.5(2DIR) U22.10(GND) U22.11(GND) U22.16(2OE_B) U23.2(GND) U24.1(GND1) U24.5(GND2) U24.10(AGND) U24.11(GND3) U24.13(TEST) U24.15(GND4) U24.25(GND5) U24.35(GND6) U24.47(GND7) U24.51(GND8) U25.1(DIR2) U25.3(GND) U26.5(VSS) U42.2(GND) U64.1(DIR2) U64.2(OE_B) U64.3(GND) U71.3(GND) X1.4(GND) X2.2(GND2) X2.4(GND1) ; also on sheet 3 4 5 11 12 13 14 15 16 17 18 19 20 21 22 23 24 25
VCC_BATT: JA1.A1 R44.1
VCCOEN_PL_M2C: JA1.A20 ; also on sheet 5
VCCOEN_PS_M2C: JA1.A19 ; also on sheet 4
CC_PL_PGOOD: Q10.1(GATE) ; also on sheet 5 16
CC_PS_PGOOD: Q8.1(GATE) ; also on sheet 4 16
EEPROM_WC_B: Q19.3(DRAIN) ; also on sheet 15
FTDI_3V3_FB: C44.2 R36.2 R41.1 U11.4(FB)
FTDI_3V3_PG: R40.2 U11.3(PG)
FTDI_EEPROM_WC: Q19.1(GATE) R262.1 U24.52(DDBUS1)
FTDI_LS_OE_B: Q13.1(GATE) R235.2 U24.22(ADBUS5)
FTDI_PS_POR_B: U24.23(ADBUS6) U71.8(A1)
FTDI_PS_POR_B_LS: R266.2 U23.1(A1) U71.5(B1)
FTDI_PS_SRST_B: U24.24(ADBUS7) U71.9(A2)
FTDI_PS_SRST_B_LS: R267.2 U23.3(A2) U71.4(B2)
FTDI_PWREN_B: R268.2 U24.60(PWREN#) U71.2(OE_B)
FTDI_TCK: U22.6(1A1) U24.16(ADBUS0)
FTDI_TDI: U22.7(1A2) U24.17(ADBUS1)
FTDI_TDO: U24.18(ADBUS2) U25.9(A2)
FTDI_TMS: U24.19(ADBUS3) U25.8(A1)
FTDI_UARTB_RXD: U24.27(BDBUS1) U64.9(A2)
FTDI_UARTB_TXD: U24.26(BDBUS0) U64.8(A1)
FWUEN_C2M_B: C236.1 JA1.C28 SW1.2(SW2)
GTH_DP0_C2M_N: JA2.B10 ; also on sheet 13
GTH_DP0_C2M_P: JA2.B9 ; also on sheet 13
GTH_DP0_M2C_N_NC: JA2.D10
GTH_DP0_M2C_P_NC: JA2.D9
GTH_DP1_C2M_N: JA2.D2 ; also on sheet 13
GTH_DP1_C2M_P: JA2.D1 ; also on sheet 13
GTH_DP1_M2C_N_NC: JA2.C8
GTH_DP1_M2C_P_NC: JA2.C7
GTH_DP2_C2M_N: JA2.B2 ; also on sheet 14
GTH_DP2_C2M_P: JA2.B1 ; also on sheet 14
GTH_DP2_M2C_N: JA2.B6 ; also on sheet 14
GTH_DP2_M2C_P: JA2.B5 ; also on sheet 14
GTH_DP3_C2M_N_NC: JA2.D6
GTH_DP3_C2M_P_NC: JA2.D5
GTH_DP3_M2C_N_NC: JA2.A4
GTH_DP3_M2C_P_NC: JA2.A3
GTH_REFCLK0_C2M_N: JA2.C4 ; also on sheet 16
GTH_REFCLK0_C2M_P: JA2.C3 ; also on sheet 16
GTH_REFCLK1_C2M_N: JA2.A8 ; also on sheet 16
GTH_REFCLK1_C2M_P: JA2.A7 ; also on sheet 16
GTR_DP0_C2M_N: JA1.A56 ; also on sheet 18
GTR_DP0_C2M_P: JA1.A55 ; also on sheet 18
GTR_DP0_M2C_N: JA1.B58 ; also on sheet 18
GTR_DP0_M2C_P: JA1.B57 ; also on sheet 18
GTR_DP1_C2M_N_NC: JA1.C56
GTR_DP1_C2M_P_NC: JA1.C55
GTR_DP1_M2C_N: JA1.A48 ; also on sheet 17
GTR_DP1_M2C_P: JA1.A47 ; also on sheet 17
GTR_DP2_C2M_N: JA1.B54 ; also on sheet 24
GTR_DP2_C2M_P: JA1.B53 ; also on sheet 24
GTR_DP2_M2C_N: JA1.D58 ; also on sheet 24
GTR_DP2_M2C_P: JA1.D57 ; also on sheet 24
GTR_DP3_C2M_N: JA1.D50 ; also on sheet 25
GTR_DP3_C2M_P: JA1.D49 ; also on sheet 25
GTR_DP3_M2C_N: JA1.C52 ; also on sheet 25
GTR_DP3_M2C_P: JA1.C51 ; also on sheet 25
GTR_REFCLK0_C2M_N: JA1.C48 ; also on sheet 16
GTR_REFCLK0_C2M_P: JA1.C47 ; also on sheet 16
GTR_REFCLK1_C2M_N: JA1.B50 ; also on sheet 16
GTR_REFCLK1_C2M_P: JA1.B49 ; also on sheet 16
GTR_REFCLK2_C2M_N: JA1.D54 ; also on sheet 16
GTR_REFCLK2_C2M_P: JA1.D53 ; also on sheet 16
GTR_REFCLK3_C2M_N_NC: JA1.A52
GTR_REFCLK3_C2M_P_NC: JA1.A51
HDA00_CC: JA1.D16 ; also on sheet 15
HDA01: JA1.D17 ; also on sheet 15
HDA02: JA1.D18 R298.1
HDA03: JA1.B16 R300.1
HDA04: JA1.B17 R302.1
HDA05: JA1.B18 R304.1
HDA06: JA1.C18 R299.1
HDA07: JA1.C19 R301.1
HDA08_CC: JA1.C20 R303.1
HDA09: JA1.A15 R305.1
HDA10: JA1.A16 ; also on sheet 14
HDA11: JA1.A17 R276.1
HDA12: JA1.D20 R278.1
HDA13: JA1.D21 R280.1
HDA14: JA1.D22 R282.1
HDA15: JA1.B20 R277.1
HDA16_CC: JA1.B21 R279.1
HDA17: JA1.B22 R281.1
HDA18: JA1.C22 R283.1
HDA19: JA1.C23 ; also on sheet 14
HDA20: JA1.C24 ; also on sheet 3
HDB00_CC: JA2.D44 ; also on sheet 11
HDB01: JA2.D45 ; also on sheet 11
HDB02: JA2.D46 ; also on sheet 11
HDB03: JA2.D48 ; also on sheet 11
HDB04: JA2.D49 ; also on sheet 11
HDB05: JA2.D50 ; also on sheet 11
HDB06: JA2.C46 ; also on sheet 11
HDB07: JA2.C47 ; also on sheet 11
HDB08_CC: JA2.C48 ; also on sheet 11
HDB09: JA2.C50 ; also on sheet 11
HDB10: JA2.C51 ; also on sheet 11
HDB11: JA2.C52 ; also on sheet 11
HDB12: JA2.B44 ; also on sheet 11
HDB13: JA2.B45 ; also on sheet 11
HDB14: JA2.B46 ; also on sheet 11
HDB15: JA2.B48 ; also on sheet 11
HDB16_CC: JA2.B49 ; also on sheet 14
HDB17: JA2.B50 ; also on sheet 14
HDB18: JA2.A46 ; also on sheet 14
HDB19: JA2.A47 ; also on sheet 14
HDB20: JA2.A48 ; also on sheet 12
HDB21: JA2.A50 ; also on sheet 12
HDB22: JA2.A51 ; also on sheet 12
HDB23: JA2.A52 ; also on sheet 12
HDC00_CC: JA2.D52 ; also on sheet 12
HDC01: JA2.D53 ; also on sheet 12
HDC02: JA2.D54 ; also on sheet 12
HDC03: JA2.D56 ; also on sheet 12
HDC04: JA2.D57 ; also on sheet 12
HDC05: JA2.D58 ; also on sheet 12
HDC06: JA2.C54 ; also on sheet 12
HDC07: JA2.C55 ; also on sheet 12
HDC08_CC: JA2.C56 ; also on sheet 12
HDC09: JA2.C58 ; also on sheet 12
HDC10: JA2.C59 ; also on sheet 12
HDC11: JA2.C60 ; also on sheet 12
HDC12: JA2.B52 ; also on sheet 12
HDC13: JA2.B53 ; also on sheet 12
HDC14: JA2.B54 ; also on sheet 12
HDC15: JA2.B56 ; also on sheet 12
HDC16_CC: JA2.B57 ; also on sheet 12
HDC17: JA2.B58 ; also on sheet 12
HDC18: JA2.A54 ; also on sheet 12
HDC19: JA2.A55 ; also on sheet 12
HDC20: JA2.A56 ; also on sheet 12
HDC21: JA2.A58 ; also on sheet 12
HDC22: JA2.A59 ; also on sheet 12
HDC23: JA2.A60 ; also on sheet 12
HPA00_CC_P_NC: JA1.C3
HPA00_CCN: JA1.C4 ; also on sheet 20
HPA01N: JA1.D8 ; also on sheet 20
HPA01P: JA1.D7 ; also on sheet 20
HPA02N: JA1.D5 ; also on sheet 20
HPA02P: JA1.D4 ; also on sheet 20
HPA03N: JA1.C7 ; also on sheet 20
HPA03P: JA1.C6 ; also on sheet 20
HPA04N: JA1.B5 ; also on sheet 20
HPA04P: JA1.B4 ; also on sheet 20
HPA05_CCN: JA1.B2 ; also on sheet 16
HPA05_CCP: JA1.B1 ; also on sheet 20
HPA06N: JA1.A4 ; also on sheet 20
HPA06P_CLK: JA1.A3 ; also on sheet 20
HPA07N: JA1.B8 ; also on sheet 20
HPA07P: JA1.B7 ; also on sheet 20
HPA08N: JA1.C10 ; also on sheet 20
HPA08P: JA1.C9 ; also on sheet 20
HPA09_N_NC: JA1.D11
HPA09P_CLK: JA1.D10 ; also on sheet 20
HPA10_CC_N_NC: JA1.C13
HPA10_CC_P_NC: JA1.C12
HPA11_N_NC: JA1.B11
HPA11_P_NC: JA1.B10
HPA12_N_NC: JA1.A10
HPA12_P_NC: JA1.A9
HPA13N: JA1.A13 ; also on sheet 14
HPA13P: JA1.A12 ; also on sheet 14
HPA14N: JA1.D14 Q23.1(GATE) R474.1
HPA14P: JA1.D13 Q22.1(GATE) R473.1
HPA_CLK0_N_NC: JA1.A7
HPA_CLK0P_CLK: JA1.A6 ; also on sheet 16
HPB00_CC_P_NC: JA2.D15
HPB00_CCN: JA2.D16 ; also on sheet 21
HPB01N: JA2.D13 ; also on sheet 21
HPB01P: JA2.D12 ; also on sheet 21
HPB02N: JA2.C18 ; also on sheet 21
HPB02P: JA2.C17 ; also on sheet 21
HPB03N: JA2.B25 ; also on sheet 21
HPB03P: JA2.B24 ; also on sheet 21
HPB04N: JA2.D22 ; also on sheet 21
HPB04P: JA2.D21 ; also on sheet 21
HPB05_CCN: JA2.B19 ; also on sheet 16
HPB05_CCP: JA2.B18 ; also on sheet 21
HPB06N: JA2.A21 ; also on sheet 21
HPB06P_CLK: JA2.A20 ; also on sheet 21
HPB07N: JA2.B16 ; also on sheet 21
HPB07P: JA2.B15 ; also on sheet 21
HPB08N: JA2.A15 ; also on sheet 21
HPB08P: JA2.A14 ; also on sheet 21
HPB09_N_NC: JA2.C12
HPB09P_CLK: JA2.C11 ; also on sheet 21
HPB10_CC_N_NC: JA2.B13
HPB10_CCP_CLK: JA2.B12 ; also on sheet 13
HPB11N: JA2.B22 ; also on sheet 13
HPB11P: JA2.B21 ; also on sheet 13
HPB12N: JA2.A18 ; also on sheet 13
HPB12P: JA2.A17 ; also on sheet 13
HPB13N: JA2.C21 ; also on sheet 13
HPB13P: JA2.C20 ; also on sheet 13
HPB14N: JA2.C15 ; also on sheet 13
HPB14P: JA2.C14 ; also on sheet 16
HPB15_CC_N_NC: JA2.A12
HPB15_CCP_CLK: JA2.A11 ; also on sheet 13
HPB16N: JA2.A24 ; also on sheet 13
HPB16P: JA2.A23 ; also on sheet 13
HPB17N: JA2.D25 ; also on sheet 13
HPB17P: JA2.D24 ; also on sheet 13
HPB18N: JA2.C24 ; also on sheet 13
HPB18P: JA2.C23 ; also on sheet 13
HPB19N: JA2.A27 ; also on sheet 13
HPB19P: JA2.A26 ; also on sheet 13
HPB_CLK0_N_NC: JA2.D19
HPB_CLK0P_CLK: JA2.D18 ; also on sheet 16
HPC00_CC_N_NC: JA2.D34
HPC00_CC_P_NC: JA2.D33
HPC01_N_NC: JA2.D31
HPC01_P_NC: JA2.D30
HPC02_N_NC: JA2.D37
HPC02_P_NC: JA2.D36
HPC03_N_NC: JA2.A42
HPC03_P_NC: JA2.A41
HPC04_N_NC: JA2.D40
HPC04_P_NC: JA2.D39
HPC05_CC_N_NC: JA2.C39
HPC05_CC_P_NC: JA2.C38
HPC06_N_NC: JA2.B28
HPC06_P_NC: JA2.B27
HPC07_N_NC: JA2.B37
HPC07_P_NC: JA2.B36
HPC08_N_NC: JA2.A30
HPC08_P_NC: JA2.A29
HPC09_N_NC: JA2.D28
HPC09_P_NC: JA2.D27
HPC10_CC_N_NC: JA2.C30
HPC10_CC_P_NC: JA2.C29
HPC11_N_NC: JA2.C33
HPC11_P_NC: JA2.C32
HPC12_N_NC: JA2.C36
HPC12_P_NC: JA2.C35
HPC13_N_NC: JA2.B31
HPC13_P_NC: JA2.B30
HPC14_N_NC: JA2.A36
HPC14_P_NC: JA2.A35
HPC15_CC_N_NC: JA2.A39
HPC15_CC_P_NC: JA2.A38
HPC16_N_NC: JA2.B34
HPC16_P_NC: JA2.B33
HPC17_N_NC: JA2.C27
HPC17_P_NC: JA2.C26
HPC18_N_NC: JA2.B40
HPC18_P_NC: JA2.B39
HPC19_N_NC: JA2.A33
HPC19_P_NC: JA2.A32
HPC_CLK0_N_NC: JA2.C42
HPC_CLK0_P_NC: JA2.C41
JTAG_TCK_C2M: J3.6(P6) JA1.A25 R66.2 R264.1
JTAG_TDI_C2M: J3.10(P10) JA1.A24 U22.14(1B2)
JTAG_TDO_M2C: J3.8(P8) JA1.A23 U25.4(B2)
JTAG_TMS_C2M: J3.4(P4) JA1.A22 U25.5(B1)
JTAG_VCCO_ON: R241.1 U22.8(2A1) U24.21(ADBUS4)
LS_OE_B: Q12.3(DRAIN) R233.2 U22.1(1OE_B) U25.2(OE_B)
MIO24_I2C_SCK: JA1.C26 ; also on sheet 15
MIO25_I2C_SDA: JA1.C27 ; also on sheet 15
MIO26: J1.1(P1) JA1.D28 R45.2
MIO27: JA1.D29 ; also on sheet 17
MIO28: JA1.D30 ; also on sheet 17
MIO29: JA1.C30 ; also on sheet 17
MIO30: JA1.C31 ; also on sheet 17
MIO31: JA1.C32 R263.1 TP37.1(TP)
MIO32_NC: JA1.A31
MIO33_NC: JA1.A32
MIO34_NC: JA1.B38
MIO35: JA1.B28 U13.7(WDI)
MIO36: JA1.B29 U64.4(B2)
MIO37: JA1.B30 U64.5(B1)
MIO38: JA1.B32 ; also on sheet 19
MIO39: JA1.B33 ; also on sheet 19
MIO40: JA1.B34 ; also on sheet 19
MIO41: JA1.A34 ; also on sheet 19
MIO42: JA1.A35 ; also on sheet 19
MIO43: JA1.A36 ; also on sheet 19
MIO44: JA1.D32 ; also on sheet 19
MIO45: JA1.D33 ; also on sheet 19
MIO46: JA1.D34 ; also on sheet 19
MIO47: JA1.C34 ; also on sheet 19
MIO48: JA1.C35 ; also on sheet 19
MIO49: JA1.C36 ; also on sheet 19
MIO50: JA1.B36 ; also on sheet 18 19
MIO51: JA1.B37 ; also on sheet 18 19
MIO52: JA1.D36 ; also on sheet 24
MIO53: JA1.D37 ; also on sheet 24
MIO54: JA1.D38 ; also on sheet 24
MIO55: JA1.C38 ; also on sheet 24
MIO56: JA1.C39 ; also on sheet 24
MIO57: JA1.C40 ; also on sheet 24
MIO58: JA1.B40 ; also on sheet 24
MIO59: JA1.B41 ; also on sheet 24
MIO60: JA1.B42 ; also on sheet 24
MIO61: JA1.A38 ; also on sheet 24
MIO62: JA1.A39 ; also on sheet 24
MIO63: JA1.A40 ; also on sheet 24
MIO64: JA1.D40 ; also on sheet 25
MIO65: JA1.D41 ; also on sheet 25
MIO66: JA1.D42 ; also on sheet 25
MIO67: JA1.C42 ; also on sheet 25
MIO68: JA1.C43 ; also on sheet 25
MIO69: JA1.C44 ; also on sheet 25
MIO70: JA1.B44 ; also on sheet 25
MIO71: JA1.B45 ; also on sheet 25
MIO72: JA1.B46 ; also on sheet 25
MIO73: JA1.A42 ; also on sheet 25
MIO74: JA1.A43 ; also on sheet 25
MIO75: JA1.A44 ; also on sheet 25
MIO76: JA1.D44 ; also on sheet 16
MIO77: JA1.D45 ; also on sheet 16
MODE0_C2M: JA1.A27 R165.1
MODE1_C2M: JA1.A28 R164.1
MODE2_C2M: JA1.A29 R163.1
MODE3_C2M: JA1.A30 R162.1
PC4_CON_PGND: J3.13(P13) Q12.1(GATE) Q13.3(DRAIN) R234.2
PL_1V8: C582.1 C585.1 C586.1 JA1.D1 JA1.D2 JA2.A44 JA2.B42 JA2.C44 JA2.D42 ; also on sheet 5 13 16 20 21
PL_3V3: C237.1 C581.1 C583.1 C584.1 JA1.B13 JA1.B14 JA2.B59 JA2.B60 JA2.D59 JA2.D60 R166.1 U42.5(IN) ; also on sheet 5 12 14 15 16 20 21
PMOD1_IO1_HDA11: C372.1 J2.1(P1) R274.2 R276.2
PMOD1_IO2_HDA12: C374.1 J2.3(P3) R278.2
PMOD1_IO3_HDA13: C377.1 J2.5(P5) R280.2
PMOD1_IO4_HDA14: C379.1 J2.7(P7) R282.2
PMOD1_IO5_HDA15: C373.1 J2.2(P2) R275.2 R277.2
PMOD1_IO6_HDA16_CC: C375.1 J2.4(P4) R279.2
PMOD1_IO7_HDA17: C378.1 J2.6(P6) R281.2
PMOD1_IO8_HDA18: C380.1 J2.8(P8) R283.2
PMOD2_IO1_HDA02: C390.1 J18.1(P1) R296.2 R298.2
PMOD2_IO2_HDA03: C392.1 J18.3(P3) R300.2
PMOD2_IO3_HDA04: C394.1 J18.5(P5) R302.2
PMOD2_IO4_HDA05: C398.1 J18.7(P7) R304.2
PMOD2_IO5_HDA06: C391.1 J18.2(P2) R297.2 R299.2
PMOD2_IO6_HDA07: C393.1 J18.4(P4) R301.2
PMOD2_IO7_HDA08_CC: C395.1 J18.6(P6) R303.2
PMOD2_IO8_HDA09: C399.1 J18.8(P8) R305.2
PMOD_3V3: C238.1 C376.1 C387.1 C396.1 C397.1 J2.11(P11) J2.12(P12) J18.11(P11) J18.12(P12) U42.1(OUT) ; also on sheet 11
PMOD_PWR_EN: R167.1 U42.4(EN)
PMOD_PWR_FLT_B: R166.2 U42.3(FLT_B)
PS_1V8: C50.1 C81.1 C91.1 C92.1 J3.2(P2) R45.1 R46.1 R47.1 R48.1 R49.1 U13.1(VDD1) U13.10(VDD2) U22.2(VCCB) U22.12(2B2) U22.13(2B1) U25.6(VCCB) U64.6(VCCB) ; also on sheet 4 15 16 17 18 19 24 25
PS_ERROR_OUT_M2C: JA1.B24 TP38.1(TP)
PS_ERROR_STATUS_M2C: JA1.B25 TP39.1(TP)
PS_POR_B: JA1.C15 U23.6(Y1) ; also on sheet 16
PS_SRST_C2M_B: J1.3(P3) J3.14(P14) JA1.C16 U23.4(Y2)
PWRGD_FPD_M2C: JA1.D24 Q7.1(GATE)
PWRGD_LPD_M2C: JA1.D25 Q17.1(GATE)
PWRGD_PL_M2C: JA1.D26 Q9.1(GATE)
PWROFF_C2M_B: JA1.B26 Q6.1(GATE) ; also on sheet 3
SOM240_1_C45_NC: JA1.C45
SOM240_1_D46_NC: JA1.D46
SOM_5V0: C323.1 C324.1 C353.1 C354.1 JA1.A59 JA1.A60 JA1.B60 JA1.C59 JA1.C60 JA1.D60 ; also on sheet 3
USB_JTAG_DM_N: J4.2(D_N) U24.7(DM) X1.2(D_N)
USB_JTAG_DM_P: J4.3(D_P) U24.8(DP) X1.1(D_P)
USB_JTAG_FLTR: C78.1 C87.1 C89.1 L4.1 R40.1 U11.5(EN) U11.8(IN)
USB_JTAG_VBUS: C88.1 J4.1(VBUS) L4.2 X1.6(VBUS)
USB_JTAG_VCORE: C95.1 C96.1 C97.1 C98.1 U24.12(VCORE1) U24.37(VOCRE2) U24.49(VREGOUT) U24.64(VCORE3)
USB_JTAG_VPHY: C82.1 C83.1 L2.2 U24.4(VPHY)
USB_JTAG_VPLL: C84.1 C85.1 L3.2 U24.9(VPLL)
USB_PWRD_VCCIO: C44.1 C79.1 C80.1 C86.1 C90.1 C93.1 C94.1 C99.1 C100.1 C101.1 C102.1 C105.1 C355.1 C356.1 L2.1 L3.1 R36.1 R74.1 R75.1 R76.1 R77.1 R233.1 R234.1 R235.1 R266.1 R267.1 R268.1 U11.1(OUT) U22.3(VCCA) U22.4(1DIR) U23.5(VCC) U24.20(VCCIO1) U24.31(VCCIO2) U24.42(VCCIO3) U24.50(VREGIN) U24.56(VCCIO4) U25.7(VCCA) U25.10(DIR1) U26.8(VCC) U64.7(VCCA) U64.10(DIR1) U71.1(DIR2) U71.6(VCCB) U71.7(VCCA) U71.10(DIR1)
UTIL_3V3: DS1.2 DS2.2 DS3.2 DS4.2 DS5.2 DS6.2 DS7.2 DS8.2 ; also on sheet 3 14
WATCHDOG_CRST: C52.1 R49.2 U13.4(CRST)
WATCHDOG_CWD: C51.1 R48.2 U13.2(CWD)
WATCHDOG_SET0: R47.2 R51.1 U13.3(SET0)
WATCHDOG_SET1: R46.2 R50.1 U13.6(SET1)
WATCHDOG_WDO_B: J1.2(P2) U13.8(WDO_B)
N1061928: R66.1 U22.15(1B1)
N1062590: J4.4(ID) X1.3(ID)
N1063364: C88.2 J4.5(GND) L5.2
N1063872: R75.2 U24.14(RESET#)
N1063914: R74.2 R78.1 U26.4(DO)
N1063918: R76.2 U24.62(EECLK) U26.2(CLK)
N1063922: R77.2 U24.63(EECS) U26.1(CS)
N1064088: R78.2 U24.61(EEDATA) U26.3(DI)
N1064220: C103.1 U24.2(OSCI) X2.1(X1)
N1064316: C104.1 U24.3(OSCO) X2.3(X3)
N1064420: R79.2 U24.6(REF)
N1690498: Q6.3(DRAIN) R157.1
N1690502: DS1.1 R157.2
N1690608: Q7.3(DRAIN) R158.1
N1690612: DS2.1 R158.2
N1690718: Q8.3(DRAIN) R159.1
N1690722: DS3.1 R159.2
N1690828: Q9.3(DRAIN) R160.1
N1690832: DS4.1 R160.2
N1690938: Q10.3(DRAIN) R161.1
N1690942: DS5.1 R161.2
N2198627: Q17.3(DRAIN) R254.1
N2198631: DS6.1 R254.2
N2549814: C344.1 R264.2
N3431689: C370.1 R274.1
N3431725: C371.1 R275.1
N3438297: C388.1 R296.1
N3438309: C389.1 R297.1
N3631918: Q22.3(DRAIN) R294.1
N3631922: DS7.1 R294.2
N3632030: Q23.3(DRAIN) R295.1
N3632034: DS8.1 R295.2

Not connected (* = marked no-connect by the designer): J3 12(P12)*; U11 2(NC1)* 7(NC2)*; U13 9(NC)*; U22 9(2A2)*; U24 28(BDBUS2)* 29(BDBUS3)* 30(BDBUS4)* 32(BDBUS5)* 33(BDBUS6)* 34(BDBUS7)* 36(SUSPEND#)* 38(CDBUS0)* 39(CDBUS1)* 40(CDBUS2)* 41(CDBUS3)* 43(CDBUS4)* 44(CDBUS5)* 45(CDBUS6)* 46(CDBUS7)* 48(DDBUS0)* 53(DDBUS2)* 54(DDBUS3)* 55(DDBUS4)* 57(DDBUS5)* 58(DDBUS6)* 59(DDBUS7)*; U26 6(ORG_NC)* 7(NC)*; X1 5(NC)*

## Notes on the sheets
sheet 6
- SOM240_1 CONNECTOR
- SOM STANDOFFS
- VCCO_HPA
- VCCO_HDA
- SOM_5V0
- Connector Decoupling
- TCK TERM
- MODE PINS
- FWUEN BUTTON
- SHUTDOWN
- PS_ERROR_OUT/STATUS
  TEST POINTS
- Quad-SPI (32b)
sheet 7
- SOM240_2 CONNECTOR
- VCCO_HPB
- VCCO_HPC
- VCCO_HPB
- VCCO_HPC
- VCCO_HDB
- VCCO_HDC
- FOUR CORNER
  MOUNTING HOLES
sheet 8
- POWER STATUS LEDS
- WATCHDOG TIMER
- Power GOOD:ON
  Power Failure:OFF
- Watchdog Timer Settings:
  Lower Boundary (Twdl max) = 920 ms
  Upper Boundary (Twdu min) = 1360 ms
  Reset Delay time (Trst min) = 635 ms
- USER DEFINED LEDS
- UF1
- Default: OFF
  High: ON
  Low: OFF
- UF2
sheet 9
- FTDI JTAG/UART
- USB_PWRD_VCCIO = 3.3V
sheet 10
- PMOD #1
- Place close to
  SOM Connector
- Place close to
  PMOD Connector
- Place close to
  SOM Connector
- Place close to
  PMOD Connector
- PMOD #2
- Place close to
  SOM Connector
- Place close to
  PMOD Connector
- Place close to
  SOM Connector
- Place close to
  PMOD Connector
